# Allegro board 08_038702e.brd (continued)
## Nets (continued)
IO_L01_13_JX2_P: JX2.1(N1) U1.AA25(IO_L1P_T0_13)
IO_L01_33_JX1_N: JX1.37(N19) U1.F4(IO_L1N_T0_33)
IO_L01_33_JX1_P: JX1.35(N18) U1.G4(IO_L1P_T0_33)
IO_L01_34_JX4_N: JX4.21(N11) U1.H11(IO_L1N_T0_34)
IO_L01_34_JX4_P: JX4.19(N10) U1.J11(IO_L1P_T0_34)
IO_L01_35_RX_D0_N: U1.E12(IO_L1N_T0_AD0N_35) U17.K11(P1_D0/RX_D0_N)
IO_L01_35_RX_D0_P: U1.F12(IO_L1P_T0_AD0P_35) U17.J12(P1_D1/RX_D0_P)
IO_L02_12_JX3_N: JX3.27(N14) U1.AC11(IO_L2N_T0_12)
IO_L02_12_JX3_P: JX3.25(N13) U1.AB12(IO_L2P_T0_12)
IO_L02_13_JX2_N: JX2.4(N2) U1.AC26(IO_L2N_T0_13)
IO_L02_13_JX2_P: JX2.2(N1) U1.AB26(IO_L2P_T0_13)
IO_L02_33_JX1_N: JX1.43(N22) U1.D3(IO_L2N_T0_33)
IO_L02_33_JX1_P: JX1.41(N21) U1.D4(IO_L2P_T0_33)
IO_L02_34_JX4_N: JX4.22(N11) U1.G5(IO_L2N_T0_34)
IO_L02_34_JX4_P: JX4.20(N10) U1.G6(IO_L2P_T0_34)
IO_L02_35_RX_D1_N: U1.D10(IO_L2N_T0_AD8N_35) U17.K10(P1_D2/RX_D1_N)
IO_L02_35_RX_D1_P: U1.E10(IO_L2P_T0_AD8P_35) U17.J11(P1_D3/RX_D1_P)
IO_L03_12_JX3_N: JX3.28(N14) U1.AA10(IO_L3N_T0_DQS_12)
IO_L03_12_JX3_P: JX3.26(N13) U1.Y10(IO_L3P_T0_DQS_12)
IO_L03_13_JX2_N: JX2.7(N4) U1.AE26(IO_L3N_T0_DQS_13)
IO_L03_13_JX2_P: JX2.5(N3) U1.AE25(IO_L3P_T0_DQS_13)
IO_L03_33_JX1_N: JX1.44(N22) U1.F2(IO_L3N_T0_DQS_33)
IO_L03_33_JX1_P: JX1.42(N21) U1.G2(IO_L3P_T0_DQS_33)
IO_L03_34_JX4_N: JX4.27(N14) U1.G9(IO_L3N_T0_DQS_34)
IO_L03_34_JX4_P: JX4.25(N13) R53.1(N1) U1.H9(PUDC_B)
IO_L03_35_RX_D2_N: U1.F10(IO_L3N_T0_DQS_AD1N_35) U17.K9(P1_D4/RX_D2_N)
IO_L03_35_RX_D2_P: U1.G10(IO_L3P_T0_DQS_AD1P_35) U17.J10(P1_D5/RX_D2_P)
IO_L04_12_JX3_N: JX3.33(N17) U1.AB10(IO_L4N_T0_12)
IO_L04_12_JX3_P: JX3.31(N16) U1.AB11(IO_L4P_T0_12)
IO_L04_13_JX2_N: JX2.8(N4) U1.AD26(IO_L4N_T0_13)
IO_L04_13_JX2_P: JX2.6(N3) U1.AD25(IO_L4P_T0_13)
IO_L04_33_JX1_N: JX1.49(N25) U1.C1(IO_L4N_T0_33)
IO_L04_33_JX1_P: JX1.47(N24) U1.D1(IO_L4P_T0_33)
IO_L04_34_JX4_N: JX4.28(N14) U1.H6(IO_L4N_T0_34)
IO_L04_34_JX4_P: JX4.26(N13) U1.H7(IO_L4P_T0_34)
IO_L04_35_RX_D3_N: U1.D11(IO_L4N_T0_35) U17.K8(P1_D6/RX_D3_N)
IO_L04_35_RX_D3_P: U1.E11(IO_L4P_T0_35) U17.J9(P1_D7/RX_D3_P)
IO_L05_12_JX3_N: JX3.44(N22) U1.Y13(IO_L5N_T0_12)
IO_L05_12_JX3_P: JX3.42(N21) U1.W13(IO_L5P_T0_12)
IO_L05_33_JX1_N: JX1.56(N3) U1.E1(IO_L5N_T0_33)
IO_L05_33_JX1_P: JX1.54(N2) U1.E2(IO_L5P_T0_33)
IO_L05_34_JX4_N: JX4.33(N17) U1.J9(IO_L5N_T0_34)
IO_L05_34_JX4_P: JX4.31(N16) U1.J10(IO_L5P_T0_34)
IO_L05_35_RX_D4_N: U1.G11(IO_L5N_T0_AD9N_35) U17.K7(P1_D8/RX_D4_N)
IO_L05_35_RX_D4_P: U1.G12(IO_L5P_T0_AD9P_35) U17.J8(P1_D9/RX_D4_P)
IO_L06_12_JX3_N: JX3.66(N8) U1.AA12(IO_L6N_T0_VREF_12)
IO_L06_12_JX3_P: JX3.64(N7) U1.AA13(IO_L6P_T0_12)
IO_L06_13_JX2_N: JX2.20(N10) U1.AB24(IO_L6N_T0_VREF_13)
IO_L06_13_JX2_P: JX2.18(N9) U1.AA24(IO_L6P_T0_13)
IO_L06_33_JX1_N: JX1.63(N7) U1.E3(IO_L6N_T0_VREF_33)
IO_L06_33_JX1_P: JX1.61(N6) U1.F3(IO_L6P_T0_33)
IO_L06_34_JX4_N: JX4.34(N17) U1.H8(IO_L6N_T0_VREF_34)
IO_L06_34_JX4_P: JX4.32(N16) U1.J8(IO_L6P_T0_34)
IO_L06_35_RX_D5_N: U1.E13(IO_L6N_T0_VREF_35) U17.J7(P1_D10/RX_D5_N)
IO_L06_35_RX_D5_P: U1.F13(IO_L6P_T0_35) U17.H8(P1_D11/RX_D5_P)
IO_L07_12_JX3_N: JX3.75(N13) U1.AD10(IO_L7N_T1_12)
IO_L07_12_JX3_P: JX3.73(N12) U1.AE10(IO_L7P_T1_12)
IO_L07_13_JX2_N: JX2.25(N13) U1.AF22(IO_L7N_T1_13)
IO_L07_13_JX2_P: JX2.23(N12) U1.AE22(IO_L7P_T1_13)
IO_L07_33_JX1_N: JX1.64(N7) U1.H1(IO_L7N_T1_33)
IO_L07_33_JX1_P: JX1.62(N6) U1.J1(IO_L7P_T1_33)
IO_L07_34_JX4_N: JX4.37(N19) U1.E5(IO_L7N_T1_34)
IO_L07_34_JX4_P: JX4.35(N18) U1.F5(IO_L7P_T1_34)
IO_L07_35_RX_FRAME_N: U1.H12(IO_L7N_T1_AD2N_35) U17.G7(RX_FRAME_N)
IO_L07_35_RX_FRAME_P: U1.H13(IO_L7P_T1_AD2P_35) U17.G8(RX_FRAME_P)
IO_L08_12_JX3_N: JX3.76(N13) U1.AF12(IO_L8N_T1_12)
IO_L08_12_JX3_P: JX3.74(N12) U1.AE12(IO_L8P_T1_12)
IO_L08_13_JX2_N: JX2.26(N13) U1.AF23(IO_L8N_T1_13)
IO_L08_13_JX2_P: JX2.24(N12) U1.AE23(IO_L8P_T1_13)
IO_L08_33_JX1_N: JX1.69(N10) U1.H3(IO_L8N_T1_33)
IO_L08_33_JX1_P: JX1.67(N9) U1.H4(IO_L8P_T1_33)
IO_L08_34_JX4_N: JX4.38(N19) U1.D8(IO_L8N_T1_34)
IO_L08_34_JX4_P: JX4.36(N18) U1.D9(IO_L8P_T1_34)
IO_L08_35_FB_CLK_N: U1.J13(IO_L8N_T1_AD10N_35) U17.G10(FB_CLK_N)
IO_L08_35_FB_CLK_P: U1.K13(IO_L8P_T1_AD10P_35) U17.F10(FB_CLK_P)
IO_L09_12_JX3_N: JX3.81(N16) U1.AF10(IO_L9N_T1_DQS_12)
IO_L09_12_JX3_P: JX3.79(N15) U1.AE11(IO_L9P_T1_DQS_12)
IO_L09_13_JX2_N: JX2.31(N16) U1.AB22(IO_L9N_T1_DQS_13)
IO_L09_13_JX2_P: JX2.29(N15) U1.AB21(IO_L9P_T1_DQS_13)
IO_L09_33_JX1_N: JX1.70(N10) U1.K1(IO_L9N_T1_DQS_33)
IO_L09_33_JX1_P: JX1.68(N9) U1.K2(IO_L9P_T1_DQS_33)
IO_L09_34_JX4_N: JX4.43(N22) U1.E8(IO_L9N_T1_DQS_34)
IO_L09_34_JX4_P: JX4.41(N21) U1.F9(IO_L9P_T1_DQS_34)
IO_L09_35_TX_FRAME_N: U1.J15(IO_L9N_T1_DQS_AD3N_35) U17.H9(TX_FRAME_N)
IO_L09_35_TX_FRAME_P: U1.K15(IO_L9P_T1_DQS_AD3P_35) U17.G9(TX_FRAME_P)
IO_L10_12_JX3_N: JX3.82(N16) U1.AF13(IO_L10N_T1_12)
IO_L10_12_JX3_P: JX3.80(N15) U1.AE13(IO_L10P_T1_12)
IO_L10_13_JX2_N: JX2.32(N16) U1.AA23(IO_L10N_T1_13)
IO_L10_13_JX2_P: JX2.30(N15) U1.AA22(IO_L10P_T1_13)
IO_L10_33_JX1_N: JX1.75(N13) U1.G1(IO_L10N_T1_33)
IO_L10_33_JX1_P: JX1.73(N12) U1.H2(IO_L10P_T1_33)
IO_L10_34_JX4_N: JX4.44(N22) U1.D5(IO_L10N_T1_34)
IO_L10_34_JX4_P: JX4.42(N21) U1.E6(IO_L10P_T1_34)
IO_L10_35_EN_AGC: U1.G16(IO_L10P_T1_AD11P_35) U17.G5(EN_AGC)
IO_L10_35_SYNC_IN: R111.2(N2) U1.G15(IO_L10N_T1_AD11N_35) U17.H5(SYNC_IN)
IO_L11_35_ENABLE: U1.G14(IO_L11P_T1_SRCC_35) U17.G6(ENABLE)
IO_L11_35_TXNRX: U1.F14(IO_L11N_T1_SRCC_35) U17.H4(TXNRX)
IO_L11_SRCC_12_JX3_N: JX3.87(N19) U1.AD11(IO_L11N_T1_SRCC_12)
IO_L11_SRCC_12_JX3_P: JX3.85(N18) U1.AC12(IO_L11P_T1_SRCC_12)
IO_L11_SRCC_13_JX2_N: JX2.37(N19) U1.AD24(IO_L11N_T1_SRCC_13)
IO_L11_SRCC_13_JX2_P: JX2.35(N18) U1.AD23(IO_L11P_T1_SRCC_13)
IO_L11_SRCC_33_JX1_N: JX1.76(N13) U1.K3(IO_L11N_T1_SRCC_33)
IO_L11_SRCC_33_JX1_P: JX1.74(N12) U1.L3(IO_L11P_T1_SRCC_33)
IO_L11_SRCC_34_JX4_N: JX4.47(N24) U1.E7(IO_L11N_T1_SRCC_34)
IO_L11_SRCC_34_JX4_P: JX4.45(N23) U1.F8(IO_L11P_T1_SRCC_34)
IO_L12_MRCC_12_JX3_N: JX3.88(N19) U1.AD13(IO_L12N_T1_MRCC_12)
IO_L12_MRCC_12_JX3_P: JX3.86(N18) U1.AC13(IO_L12P_T1_MRCC_12)
IO_L12_MRCC_13_JX2_N: JX2.38(N19) U1.AC24(IO_L12N_T1_MRCC_13)
IO_L12_MRCC_13_JX2_P: JX2.36(N18) U1.AC23(IO_L12P_T1_MRCC_13)
IO_L12_MRCC_33_JX1_N: JX1.83(N17) U1.J3(IO_L12N_T1_MRCC_33)
IO_L12_MRCC_33_JX1_P: JX1.81(N16) U1.J4(IO_L12P_T1_MRCC_33)
IO_L12_MRCC_34_JX4_N: JX4.48(N24) U1.F7(IO_L12N_T1_MRCC_34)
IO_L12_MRCC_34_JX4_P: JX4.46(N23) U1.G7(IO_L12P_T1_MRCC_34)
IO_L12_MRCC_35_DATA_CLK_N: U1.H14(IO_L12N_T1_MRCC_35) U17.H11(DATA_CLK_N)
IO_L12_MRCC_35_DATA_CLK_P: U1.J14(IO_L12P_T1_MRCC_35) U17.G11(DATA_CLK_P)
IO_L13_35_TX_D0_N: U1.D14(IO_L13N_T2_MRCC_35) U17.E12(P0_D0/TX_D0_N)
IO_L13_35_TX_D0_P: U1.D15(IO_L13P_T2_MRCC_35) U17.D11(P0_D1/TX_D0_P)
IO_L13_MRCC_12_JX3_N: JX3.93(N22) U1.AD14(IO_L13N_T2_MRCC_12)
IO_L13_MRCC_12_JX3_P: JX3.91(N21) U1.AC14(IO_L13P_T2_MRCC_12)
IO_L13_MRCC_13_JX2_N: JX2.43(N22) U1.AD21(IO_L13N_T2_MRCC_13)
IO_L13_MRCC_13_JX2_P: JX2.41(N21) U1.AD20(IO_L13P_T2_MRCC_13)
IO_L13_MRCC_33_JX1_N: JX1.84(N17) U1.M5(IO_L13N_T2_MRCC_33)
IO_L13_MRCC_33_JX1_P: JX1.82(N16) U1.M6(IO_L13P_T2_MRCC_33)
IO_L13_MRCC_34_JX4_N: JX4.53(N2) U1.C7(IO_L13N_T2_MRCC_34)
IO_L13_MRCC_34_JX4_P: JX4.51(N1) U1.C8(IO_L13P_T2_MRCC_34)
IO_L14_35_TX_D1_N: U1.E15(IO_L14N_T2_AD4N_SRCC_35) U17.E11(P0_D2/TX_D1_N)
IO_L14_35_TX_D1_P: U1.F15(IO_L14P_T2_AD4P_SRCC_35) U17.D10(P0_D3/TX_D1_P)
IO_L14_SRCC_12_JX3_N: JX3.94(N22) U1.AB14(IO_L14N_T2_SRCC_12)
IO_L14_SRCC_12_JX3_P: JX3.92(N21) U1.AB15(IO_L14P_T2_SRCC_12)
IO_L14_SRCC_13_JX2_N: JX2.44(N22) U1.AC22(IO_L14N_T2_SRCC_13)
IO_L14_SRCC_13_JX2_P: JX2.42(N21) U1.AC21(IO_L14P_T2_SRCC_13)
IO_L14_SRCC_33_JX1_N: JX1.50(N25) U1.L4(IO_L14N_T2_SRCC_33)
IO_L14_SRCC_33_JX1_P: JX1.48(N24) U1.L5(IO_L14P_T2_SRCC_33)
IO_L14_SRCC_34_JX4_N: JX4.54(N2) U1.C6(IO_L14N_T2_SRCC_34)
IO_L14_SRCC_34_JX4_P: JX4.52(N1) U1.D6(IO_L14P_T2_SRCC_34)
IO_L15_12_JX3_N: JX3.99(N25) U1.AD15(IO_L15N_T2_DQS_12)
IO_L15_12_JX3_P: JX3.97(N24) U1.AD16(IO_L15P_T2_DQS_12)
IO_L15_13_JX2_N: JX2.49(N25) U1.AF20(IO_L15N_T2_DQS_13)
IO_L15_13_JX2_P: JX2.47(N24) U1.AF19(IO_L15P_T2_DQS_13)
IO_L15_33_JX1_N: JX1.55(N3) U1.N2(IO_L15N_T2_DQS_33)
IO_L15_33_JX1_P: JX1.53(N2) U1.N3(IO_L15P_T2_DQS_33)
IO_L15_34_JX4_N: JX4.59(N5) U1.B9(IO_L15N_T2_DQS_34)
IO_L15_34_JX4_P: JX4.57(N4) U1.C9(IO_L15P_T2_DQS_34)
IO_L15_35_TX_D2_N: U1.C16(IO_L15N_T2_DQS_AD12N_35) U17.E10(P0_D4/TX_D2_N)
IO_L15_35_TX_D2_P: U1.C17(IO_L15P_T2_DQS_AD12P_35) U17.D9(P0_D5/TX_D2_P)
IO_L16_12_JX3_N: JX3.100(N25) U1.AF14(IO_L16N_T2_12)
IO_L16_12_JX3_P: JX3.98(N24) U1.AF15(IO_L16P_T2_12)
IO_L16_13_JX2_N: JX2.50(N25) U1.AE21(IO_L16N_T2_13)
IO_L16_13_JX2_P: JX2.48(N24) U1.AE20(IO_L16P_T2_13)
IO_L16_33_JX1_N: JX1.13(N7) U1.L2(IO_L16N_T2_33)
IO_L16_33_JX1_P: JX1.11(N6) U1.M2(IO_L16P_T2_33)
IO_L16_34_JX4_N: JX4.60(N5) U1.A10(IO_L16N_T2_34)
IO_L16_34_JX4_P: JX4.58(N4) U1.B10(IO_L16P_T2_34)
IO_L16_35_TX_D3_N: U1.D16(IO_L16N_T2_35) U17.E9(P0_D6/TX_D3_N)
IO_L16_35_TX_D3_P: U1.E16(IO_L16P_T2_35) U17.D8(P0_D7/TX_D3_P)
IO_L17_12_JX2_N: JX2.84(N17) U1.AE15(IO_L17N_T2_12)
IO_L17_12_JX2_P: JX2.82(N16) U1.AE16(IO_L17P_T2_12)
IO_L17_13_JX2_N: JX2.55(N3) U1.AD19(IO_L17N_T2_13)
IO_L17_13_JX2_P: JX2.53(N2) U1.AD18(IO_L17P_T2_13)
IO_L17_33_JX1_N: JX1.14(N7) U1.M4(IO_L17N_T2_33)
IO_L17_33_JX1_P: JX1.12(N6) U1.N4(IO_L17P_T2_33)
IO_L17_34_JX4_N: JX4.69(N10) U1.A8(IO_L17N_T2_34)
IO_L17_34_JX4_P: JX4.67(N9) U1.A9(IO_L17P_T2_34)
IO_L17_35_TX_D4_N: U1.B15(IO_L17N_T2_AD5N_35) U17.E8(P0_D8/TX_D4_N)
IO_L17_35_TX_D4_P: U1.B16(IO_L17P_T2_AD5P_35) U17.D7(P0_D9/TX_D4_P)
IO_L18_12_JX2_N: JX2.83(N17) U1.AF17(IO_L18N_T2_12)
IO_L18_12_JX2_P: JX2.81(N16) U1.AE17(IO_L18P_T2_12)
IO_L18_13_JX2_N: JX2.56(N3) U1.AF18(IO_L18N_T2_13)
IO_L18_13_JX2_P: JX2.54(N2) U1.AE18(IO_L18P_T2_13)
IO_L18_33_JX1_N: JX1.19(N10) U1.M1(IO_L18N_T2_33)
IO_L18_33_JX1_P: JX1.17(N9) U1.N1(IO_L18P_T2_33)
IO_L18_34_JX4_N: JX4.70(N10) U1.A7(IO_L18N_T2_34)
IO_L18_34_JX4_P: JX4.68(N9) U1.B7(IO_L18P_T2_34)
IO_L18_35_TX_D5_N: U1.A17(IO_L18N_T2_AD13N_35) U17.F8(P0_D10/TX_D5_N)
IO_L18_35_TX_D5_P: U1.B17(IO_L18P_T2_AD13P_35) U17.E7(P0_D11/TX_D5_P)
IO_L19_12_JX2_N: JX2.90(N20) U1.AA17(IO_L19N_T3_VREF_12)
IO_L19_12_JX2_P: JX2.88(N19) U1.Y17(IO_L19P_T3_12)
IO_L19_13_JX2_N: JX2.63(N7) U1.Y20(IO_L19N_T3_VREF_13)
IO_L19_13_JX2_P: JX2.61(N6) U1.W20(IO_L19P_T3_13)
IO_L19_33_JX1_N: JX1.20(N10) U1.L7(IO_L19N_T3_VREF_33)
IO_L19_33_JX1_P: JX1.18(N9) U1.M7(IO_L19P_T3_33)
IO_L19_34_JX4_N: JX4.75(N13) U1.C3(IO_L19N_T3_VREF_34)
IO_L19_34_JX4_P: JX4.73(N12) U1.C4(IO_L19P_T3_34)
IO_L19_35_CTRL_OUT0: U1.D13(IO_L19P_T3_35) U17.D4(CTRL_OUT0)
IO_L19_35_CTRL_OUT1: U1.C13(IO_L19N_T3_VREF_35) U17.E4(CTRL_OUT1)
IO_L20_12_JX2_N: JX2.89(N20) U1.AB16(IO_L20N_T3_12)
IO_L20_12_JX2_P: JX2.87(N19) U1.AB17(IO_L20P_T3_12)
IO_L20_13_JX2_N: JX2.64(N7) U1.AB20(IO_L20N_T3_13)
IO_L20_13_JX2_P: JX2.62(N6) U1.AA20(IO_L20P_T3_13)
IO_L20_33_JX1_N: JX1.25(N13) U1.J5(IO_L20N_T3_33)
IO_L20_33_JX1_P: JX1.23(N12) U1.K5(IO_L20P_T3_33)
IO_L20_34_JX4_N: JX4.76(N13) U1.B4(IO_L20N_T3_34)
IO_L20_34_JX4_P: JX4.74(N12) U1.B5(IO_L20P_T3_34)
IO_L20_35_CTRL_OUT2: U1.C14(IO_L20P_T3_AD6P_35) U17.E5(CTRL_OUT2)
IO_L20_35_CTRL_OUT3: U1.B14(IO_L20N_T3_AD6N_35) U17.E6(CTRL_OUT3)
IO_L21_12_JX2_N: JX2.95(N23) U1.AC16(IO_L21N_T3_DQS_12)
IO_L21_12_JX2_P: JX2.93(N22) U1.AC17(IO_L21P_T3_DQS_12)
IO_L21_13_JX2_N: JX2.69(N10) U1.AC19(IO_L21N_T3_DQS_13)
IO_L21_13_JX2_P: JX2.67(N9) U1.AC18(IO_L21P_T3_DQS_13)
IO_L21_33_JX1_N: JX1.26(N13) U1.L8(IO_L21N_T3_DQS_33)
IO_L21_33_JX1_P: JX1.24(N12) U1.M8(IO_L21P_T3_DQS_33)
IO_L21_34_JX4_N: JX4.79(N15) U1.A5(IO_L21N_T3_DQS_34)
IO_L21_34_JX4_P: JX4.77(N14) U1.B6(IO_L21P_T3_DQS_34)
IO_L21_35_CTRL_OUT4: U1.A15(IO_L21P_T3_DQS_AD14P_35) U17.F6(CTRL_OUT4)
IO_L21_35_CTRL_OUT5: U1.A14(IO_L21N_T3_DQS_AD14N_35) U17.F5(CTRL_OUT5)
IO_L22_12_JX2_N: JX2.96(N23) U1.AA14(IO_L22N_T3_12)
IO_L22_12_JX2_P: JX2.94(N22) U1.AA15(IO_L22P_T3_12)
IO_L22_13_JX2_N: JX2.70(N10) U1.AB19(IO_L22N_T3_13)
IO_L22_13_JX2_P: JX2.68(N9) U1.AA19(IO_L22P_T3_13)
IO_L22_33_JX1_N: JX1.31(N16) U1.J6(IO_L22N_T3_33)
IO_L22_33_JX1_P: JX1.29(N15) U1.K6(IO_L22P_T3_33)
IO_L22_34_JX4_N: JX4.80(N15) U1.A3(IO_L22N_T3_34)
IO_L22_34_JX4_P: JX4.78(N14) U1.A4(IO_L22P_T3_34)
IO_L22_35_CTRL_OUT6: U1.C12(IO_L22P_T3_AD7P_35) U17.F4(CTRL_OUT6)
IO_L22_35_CTRL_OUT7: U1.B12(IO_L22N_T3_AD7N_35) U17.G4(CTRL_OUT7)
IO_L23_12_JX2_N: JX2.99(N25) U1.Y15(IO_L23N_T3_12)
IO_L23_12_JX2_P: JX2.97(N24) U1.Y16(IO_L23P_T3_12)
IO_L23_13_JX2_N: JX2.75(N13) U1.W19(IO_L23N_T3_13)
IO_L23_13_JX2_P: JX2.73(N12) U1.W18(IO_L23P_T3_13)
IO_L23_33_JX1_N: JX1.32(N16) U1.N6(IO_L23N_T3_33)
IO_L23_33_JX1_P: JX1.30(N15) U1.N7(IO_L23P_T3_33)
IO_L23_34_CTRL_IN0: U1.C2(IO_L23P_T3_34) U22.13(B0)
IO_L23_34_CTRL_IN1: U1.B1(IO_L23N_T3_34) U22.12(B1)
IO_L23_35_SPI_CLK: U1.B11(IO_L23N_T3_35) U17.J5(SPI_CLK)
IO_L23_35_SPI_ENB: U1.C11(IO_L23P_T3_35) U17.K6(SPI_ENB)
IO_L24_12_JX4_N: JX4.15(N8) U1.W15(IO_L24N_T3_12)
IO_L24_12_JX4_P: JX4.13(N7) U1.W16(IO_L24P_T3_12)
IO_L24_13_JX2_N: JX2.76(N13) U1.AA18(IO_L24N_T3_13)
IO_L24_13_JX2_P: JX2.74(N12) U1.Y18(IO_L24P_T3_13)
IO_L24_33_JX1_N: JX1.38(N19) U1.K7(IO_L24N_T3_33)
IO_L24_33_JX1_P: JX1.36(N18) U1.K8(IO_L24P_T3_33)
IO_L24_34_CTRL_IN2: U1.B2(IO_L24P_T3_34) U22.11(B2)
IO_L24_34_CTRL_IN3: U1.A2(IO_L24N_T3_34) U22.10(B3)
IO_L24_35_SPI_DI: U1.A13(IO_L24P_T3_AD15P_35) U17.J4(SPI_DI)
IO_L24_35_SPI_DO: U1.A12(IO_L24N_T3_AD15N_35) U17.L6(SPI_DO)
J3-9: J3.9(N9) R36.2(N2) U5.7(S2B)
JTAG_TCK: JX1.1(N1) U1.W12(TCK_0)
JTAG_TDI: JX1.4(N2) U1.V11(TDI_0)
JTAG_TDO: JX1.3(N2) U1.W10(TDO_0)
JTAG_TMS: JX1.2(N1) U1.W11(TMS_0)
JX3_SD1_CDN: JX3.41(N21) U5.9(S2A)
JX_MGTAVCC: JX3.5(N3) JX3.7(N4) JX3.9(N5) JX3.11(N6) Q8.1(D1) Q8.2(D2) Q8.5(D3) Q8.6(D4) U7.3(VX3)
JX_MGTAVTT: JX3.30(N15) JX3.32(N16) Q7.1(D1) Q7.2(D2) Q7.5(D3) Q7.6(D4) U7.4(VX4)
JX_VCCO_12: JX1.78(N14) JX1.79(N15) JX1.80(N15) Q11.1(D1) Q11.2(D2) Q11.5(D3) Q11.6(D4) Q11.PAD1(D5) R70.1(N1)
JX_VCCO_12_SEQ: R69.1(N1) R70.2(N2) U7.7(VP2)
JX_VCCO_13: JX2.98(N24) JX3.45(N23) JX3.46(N23) Q9.1(D1) Q9.2(D2) Q9.5(D3) Q9.6(D4) Q9.PAD1(D5) R72.1(N1)
JX_VCCO_13_SEQ: R71.1(N1) R72.2(N2) U7.8(VP3)
JX_VCCO_33_34: JX2.78(N14) JX2.79(N15) JX2.80(N15) Q10.1(D1) Q10.2(D2) Q10.5(D3) Q10.6(D4) R73.1(N1)
JX_VCCO_33_34_SEQ: R73.2(N2) R74.1(N1) U7.9(VP4)
JX_VIN: D1.1(N1) JX1.57(N4) JX1.58(N4) JX1.59(N5) JX1.60(N5) JX2.12(N6) JX2.57(N4) JX2.58(N4) JX2.59(N5) JX2.60(N5) Q13.1(D1) Q13.2(D2) Q13.5(D3) Q13.6(D4) Q13.PAD1(D5)
MGTAVCC: C64.1(N1) C220.1(N1) C222.1(N1) C227.1(N1) C229.1(N1) C231.1(N1) C233.1(N1) C235.1(N1) C237.1(N1) C239.1(N1) Q8.4(S) U1.AA4(MGTAVCC1) U1.AA8(MGTAVCC2) U1.AB6(MGTAVCC3) U1.AC8(MGTAVCC4) U1.AD6(MGTAVCC5) U1.AE8(MGTAVCC6) U1.R4(MGTAVCC7) U1.T6(MGTAVCC8) U1.U4(MGTAVCC9) U1.Y6(MGTAVCC10)
MGTAVCC_EN: Q8.3(G) U7.25(PDO6)
MGTAVTT: C221.1(N1) C223.1(N1) C228.1(N1) C230.1(N1) C232.1(N1) C234.1(N1) C236.1(N1) C238.1(N1) C240.1(N1) C241.1(N1) Q7.4(S) R10.1(N1) U1.AB2(MGTAVTT1) U1.AB7(MGTAVTTRCAL_112) U1.AC4(MGTAVTT2) U1.AD2(MGTAVTT3) U1.AE4(MGTAVTT4) U1.AF2(MGTAVTT5) U1.AF6(MGTAVTT6) U1.T2(MGTAVTT7) U1.V2(MGTAVTT8) U1.W4(MGTAVTT9) U1.Y2(MGTAVTT10)
MGTAVTT_EN: Q7.3(G) U7.26(PDO5)
MGTREFCLK0_112_JX1_N: C45.1(N1) JX1.89(N20)
MGTREFCLK0_112_JX1_P: C47.1(N1) JX1.87(N19)
MGTREFCLK1_112_JX3_N: C48.1(N1) JX3.4(N2)
MGTREFCLK1_112_JX3_P: C46.1(N1) JX3.2(N1)
MGTXRX0_112_JX1_N: JX1.90(N20) U1.AB3(MGTXRXN0_112)
MGTXRX0_112_JX1_P: JX1.88(N19) U1.AB4(MGTXRXP0_112)
MGTXRX1_112_JX1_N: JX1.93(N22) U1.Y3(MGTXRXN1_112)
MGTXRX1_112_JX1_P: JX1.91(N21) U1.Y4(MGTXRXP1_112)
MGTXRX2_112_JX1_N: JX1.94(N22) U1.V3(MGTXRXN2_112)
MGTXRX2_112_JX1_P: JX1.92(N21) U1.V4(MGTXRXP2_112)
MGTXRX3_112_JX1_N: JX1.99(N25) U1.T3(MGTXRXN3_112)
MGTXRX3_112_JX1_P: JX1.97(N24) U1.T4(MGTXRXP3_112)
MGTXTX0_112_JX3_N: JX3.10(N5) U1.AA1(MGTXTXN0_112)
MGTXTX0_112_JX3_P: JX3.8(N4) U1.AA2(MGTXTXP0_112)
MGTXTX1_112_JX3_N: JX3.15(N8) U1.W1(MGTXTXN1_112)
MGTXTX1_112_JX3_P: JX3.13(N7) U1.W2(MGTXTXP1_112)
MGTXTX2_112_JX3_N: JX3.16(N8) U1.U1(MGTXTXN2_112)
MGTXTX2_112_JX3_P: JX3.14(N7) U1.U2(MGTXTXP2_112)
MGTXTX3_112_JX3_N: JX3.21(N11) U1.R1(MGTXTXN3_112)
MGTXTX3_112_JX3_P: JX3.19(N10) U1.R2(MGTXTXP3_112)
PG_1P8V: JX2.10(N5) R81.1(N1) U4.1(PG3) U19.4(EN) U20.4(EN)
PG_MODULE: JX2.11(N6) Q14.1(G) R43.2(N2) U7.21(PDO10)
PHY1_1V8: C74.1(N1) C78.1(N1) C206.1(N1) C212.1(N1) E14.2(N2) R11.1(N1) U10.10(VDDO_SEL) U10.11(VDDO_1) U10.49(VDDO_2) U10.52(VDDO_3)
PHY1_AVDD_1V8: C201.1(N1) C203.1(N1) C210.1(N1) C211.1(N1) C218.1(N1) C219.1(N1) U10.3(AVDD18_1) U10.19(AVDD18_2) U10.26(AVDD18_3) U10.35(AVDDC18) U10.38(AVDD18_4) U10.39(AVDD18_OUT) U24.5(VIN7)
PHY1_AVDD_3V3: C49.1(N1) C208.1(N1) C214.1(N1) C217.1(N1) E15.2(N2) U10.20(AVDD33_1) U10.25(AVDD33_2)
PHY1_DVDD_1V0: C58.1(N1) C63.1(N1) C73.1(N1) C75.1(N1) U10.6(DVDD_1) U10.40(DVDD_OUT) U10.42(DVDD_2)
PHY1_LED_0: Q2.1(G) R14.1(N1) U10.14(LED(0))
PHY1_LED_1: Q1.1(G) R13.1(N1) U10.13(LED(1))
PHY1_VDD_3V3: C50.1(N1) C224.1(N1) C225.1(N1) C226.1(N1) E16.2(N2) R15.1(N1) R16.1(N1) U10.36(REG_IN)
PS-SRST#: Q5.2(S) R7.2(N2) R19.1(N1) U1.A22(PS_SRST_B_501)
PS_1.35V_EN: U4.7(EN2) U7.22(PDO9)
PS_MIO00_500_JX4: JX4.97(N24) U1.E26(PS_MIO0_500)
PS_MIO01_500_QSPI0_SS_B: R28.2(N2) U1.D26(PS_MIO1_500) U13.C2(S#)
PS_MIO02_500_QSPI0_IO0: R120.1(N1) U1.E25(PS_MIO2_500) U13.D3(DQ0)
PS_MIO03_500_QSPI0_IO1: R119.1(N1) U1.D25(PS_MIO3_500) U13.D2(DQ1)
PS_MIO04_500_QSPI0_IO2: R121.1(N1) U1.F24(PS_MIO4_500) U13.C4(W#/VPP/DQ2)
PS_MIO05_500_QSPI0_IO3: R122.1(N1) U1.C26(PS_MIO5_500) U13.D4(HOLD#/DQ3)
PS_MIO06_500_QSPI0_SCLK: R116.1(N1) U1.F23(PS_MIO6_500) U13.B2(C)
PS_MIO07_500_USB_RESET_B: R31.2(N2) U1.E23(PS_MIO7_500) U15.27(RESETB)
PS_MIO08_500_ETH0_RESETN: R32.2(N2) U1.A24(PS_MIO8_500) U10.16(RESETN)
PS_MIO09_500_USB_CLK_PD: R27.1(N1) U1.D24(PS_MIO9_500) Y3.1(STANDBY)
PS_MIO10_500_JX4: JX4.87(N19) U1.A25(PS_MIO10_500)
PS_MIO11_500_JX4: JX4.88(N19) U1.B26(PS_MIO11_500)
PS_MIO12_500_JX4: JX4.86(N18) R60.2(N2)
PS_MIO13_500_JX4: JX4.91(N21) U1.B25(PS_MIO13_500)
PS_MIO14_500_JX4: JX4.93(N22) U1.D23(PS_MIO14_500)
PS_MIO15_500_JX4: JX4.85(N18) U1.C24(PS_MIO15_500)
PS_MIO16_501_ETH0_TX_CLK: U1.G21(PS_MIO16_501) U10.53(TX_CLK)
PS_MIO17_501_ETH0_TX_D0: U1.G17(PS_MIO17_501) U10.50(TXD(0))
PS_MIO18_501_ETH0_TX_D1: U1.G20(PS_MIO18_501) U10.51(TXD(1))
PS_MIO19_501_ETH0_TX_D2: U1.G19(PS_MIO19_501) U10.54(TXD(2))
PS_MIO20_501_ETH0_TX_D3: U1.H19(PS_MIO20_501) U10.55(TXD(3))
PS_MIO21_501_ETH0_TX_CTL: U1.F22(PS_MIO21_501) U10.56(TX_CTRL)
PS_MIO22_501_ETH0_RX_CLK: U1.G22(PS_MIO22_501) U10.46(RX_CLK)
PS_MIO23_501_ETH0_RX_D0: U1.F20(PS_MIO23_501) U10.44(RXD(0))
PS_MIO24_501_ETH0_RX_D1: U1.J19(PS_MIO24_501) U10.45(RXD(1))
PS_MIO25_501_ETH0_RX_D2: U1.F19(PS_MIO25_501) U10.47(RXD(2))
PS_MIO26_501_ETH0_RX_D3: U1.H17(PS_MIO26_501) U10.48(RXD(3))
PS_MIO27_501_ETH0_RX_CTL: U1.F18(PS_MIO27_501) U10.43(RX_CTRL)
PS_MIO28_501_USB0_D4: U1.J18(PS_MIO28_501) U15.7(DATA4)
PS_MIO29_501_USB0_DIR: U1.E20(PS_MIO29_501) U15.31(DIR)
PS_MIO30_501_USB0_STP: U1.K19(PS_MIO30_501) U15.29(STP)
PS_MIO31_501_USB0_NXT: U1.E21(PS_MIO31_501) U15.2(NXT)
PS_MIO32_501_USB0_D0: U1.K17(PS_MIO32_501) U15.3(DATA0)
PS_MIO33_501_USB0_D1: U1.E22(PS_MIO33_501) U15.4(DATA1)
PS_MIO34_501_USB0_D2: U1.J16(PS_MIO34_501) U15.5(DATA2)
PS_MIO35_501_USB0_D3: U1.D19(PS_MIO35_501) U15.6(DATA3)
PS_MIO36_501_USB0_CLK: U1.K16(PS_MIO36_501) U15.1(CLKOUT)
PS_MIO37_501_USB0_D5: U1.D20(PS_MIO37_501) U15.9(DATA5)
PS_MIO38_501_USB0_D6: U1.D21(PS_MIO38_501) U15.10(DATA6)
PS_MIO39_501_USB0_D7: U1.C21(PS_MIO39_501) U15.13(DATA7)
PS_MIO40_501_SD0_CLK: U1.C22(PS_MIO40_501) U11.9(CLKA)
PS_MIO41_501_SD0_CMD: U1.C19(PS_MIO41_501) U11.4(CMDA)
PS_MIO42_501_SD0_DATA0: U1.F17(PS_MIO42_501) U11.6(DAT0A)
PS_MIO43_501_SD0_DATA1: U1.D18(PS_MIO43_501) U11.7(DAT1A)
PS_MIO44_501_SD0_DATA2: U1.E18(PS_MIO44_501) U11.1(DAT2A)
PS_MIO45_501_SD0_DATA3: U1.C18(PS_MIO45_501) U11.3(DAT3A)
PS_MIO46_501_JX4: JX4.92(N21) R37.2(N2) U1.E17(PS_MIO46_501)
PS_MIO47_501_JX4: JX4.94(N22) R26.1(N1) U1.B19(PS_MIO47_501)
PS_MIO48_501_JX4: JX4.99(N25) U1.B21(PS_MIO48_501)
PS_MIO49_501_JX4: JX4.98(N24) U1.A18(PS_MIO49_501)
PS_MIO50_501_SD0_CD: U1.B22(PS_MIO50_501) U5.8(D2)
PS_MIO51_501_JX4: JX4.100(N25) U1.B20(PS_MIO51_501)
PS_MIO52_501_ETH0_MDC: U1.A20(PS_MIO52_501) U10.7(MDC)
PS_MIO53_501_ETH0_MDIO: R11.2(N2) U1.A19(PS_MIO53_501) U10.8(MDIO)
PWR_ENABLE: JX1.5(N3) R56.2(N2) U4.12(EN1) U18.20(EN)
PWR_GD: R306.1(N1) U7.37(AUX2) U9.7(PG) U19.5(PG) U20.5(PG)
PWR_GD_1.35V: R3.2(N2) R29.2(N2) SW1.1A(N1) SW1.1B(N2) U1.C23(PS_POR_B_500) U4.2(PG2) U4.6(PG1) U18.21(PGOOD)
REF_IN_OUT: C202.1(N1) U7.13(REFIN) U7.14(REFOUT)
RX1A_N: C8.2(N2) U17.M2(RX1A_N)
RX1A_P: C9.2(N2) U17.M1(RX1A_P)
RX1B_N: C51.2(N2) U17.J1(RX1B_N)
RX1B_P: C52.2(N2) U17.H1(RX1B_P)
RX2A_N: C10.2(N2) U17.A1(RX2A_N)
RX2A_P: C11.2(N2) U17.A2(RX2A_P)
RX2B_N: C53.2(N2) U17.F1(RX2B_N)
RX2B_P: C56.2(N2) U17.E1(RX2B_P)
S_IN_N: JP2.3(B) U10.2(S_INN)
S_IN_P: JP1.3(B) U10.1(S_INP)
S_OUT_N: JP4.3(B) U10.5(S_OUTN)
S_OUT_P: JP3.3(B) U10.4(S_OUTP)
SCL: JX2.17(N9) R58.2(N2) U1.AF24(IO_L5P_T0_13) U21.2(SCLA)
SCL_ADM1166: P1.A4(N4A) P1.B4(N4B) R51.2(N2) U7.35(SCL) U21.7(SCLB) U24.15(SCL)
SD_SEL: S1.2(C) U5.5(IN2) U11.24(SEL)
SDA: JX2.19(N10) R57.2(N2) U1.AF25(IO_L5N_T0_13) U21.3(SDAA)
SDA_ADM1166: P1.A3(N3A) P1.B3(N3B) R52.2(N2) U7.36(SDA) U21.6(SDAB) U24.14(SDA)
SDIO_CLKB0: J3.5(N5) U11.19(CLKB0)
SDIO_CLKB1: JX3.43(N22) U11.13(CLKB1)
SDIO_CMDB0: J3.3(N3) R109.2(N2) U11.20(CMDB0)
SDIO_CMDB1: JX3.34(N17) R4.2(N2) U11.12(CMDB1)
SDIO_DAT0B0: J3.7(N7) U11.18(DAT0B0)
SDIO_DAT0B1: JX3.37(N19) U11.14(DAT0B1)
SDIO_DAT1B0: J3.8(N8) U11.16(DAT1B0)
SDIO_DAT1B1: JX3.36(N18) U11.15(DAT1B1)
SDIO_DAT2B0: J3.1(N1) U11.23(DAT2B0)
SDIO_DAT2B1: JX3.39(N20) U11.8(DAT2B1)
SDIO_DAT3B0: J3.2(N2) U11.22(DAT3B0)
SDIO_DAT3B1: JX3.38(N19) U11.10(DAT3B1)
SW1: L5.1(N1) U4.15(SW1)
SW2: L6.1(N1) U4.4(SW2)
SW3: L7.1(N1) U4.20(SW3)
TX1A_N: C25.1(N1) L8.2(N2) U17.M8(TX1A_N)
TX1A_P: C26.1(N1) L9.2(N2) U17.M7(TX1A_P)
TX1B_N: C29.1(N1) L1.2(N2) U17.M10(TX1B_N)
TX1B_P: C30.1(N1) L2.2(N2) U17.M9(TX1B_P)
TX2A_N: C32.1(N1) L10.2(N2) U17.A7(TX2A_N)
TX2A_P: C33.1(N1) L11.2(N2) U17.A8(TX2A_P)
TX2B_N: C34.1(N1) L3.2(N2) U17.A9(TX2B_N)
TX2B_P: C35.1(N1) L4.2(N2) U17.A10(TX2B_P)
TX_MON1: C6.2(N2) U17.M5(TX_MON1)
TX_MON2: C7.2(N2) U17.A5(TX_MON2)
TX_VCO_1P1V_SUPPLY: C104.2(N2) R123.1(N1) U17.A11(VDDA1P1_TX_VCO) U17.B11(TX_VCO_LDO_OUT)
UNNAMED_2_CAP_I87_N1: C242.1(N1) U10.41(REGCAP2)
UNNAMED_2_CAP_I87_N2: C242.2(N2) U10.37(REGCAP1)
UNNAMED_2_CAP_I88_N1: C60.1(N1) U10.34(XTAL_IN) Y2.3(N2)
UNNAMED_2_CAP_I90_N1: C59.1(N1) U10.33(XTAL_OUT) Y2.1(N1)
UNNAMED_2_DIO6PV8_I47_REF1: R178.2(N2) U16.2(REF1)
UNNAMED_2_IC88E151X_I86_CONFIG: R12.2(N2) U10.15(CONFIG)
UNNAMED_2_IC88E151X_I86_RSET: R50.1(N1) U10.30(RSET)
UNNAMED_2_ICUSB3320C_I42_RBIAS: R176.1(N1) U15.24(RBIAS)
UNNAMED_2_ICUSB3320C_I42_REFCLK: R175.1(N1) U15.26(REFCLK)
UNNAMED_2_ICXC7Z035_I20_PSMIOVR: R191.1(N1) R194.2(N2) U1.H18(PS_MIO_VREF_501)
UNNAMED_2_RES_I50_N2: R175.2(N2) Y3.3(OUTPUT)
UNNAMED_2_RES_I105_N1: Q4.3(D) R18.1(N1)
UNNAMED_2_RES_I108_N2: Q2.3(D) Q4.1(G) R16.2(N2)
UNNAMED_2_RES_I112_N1: Q3.3(D) R17.1(N1)
UNNAMED_2_RES_I114_N2: Q1.3(D) Q3.1(G) R15.2(N2)
UNNAMED_3_ADM1166_I104_A0: R30.2(N2) R38.1(N1) U7.33(A0)
UNNAMED_3_ADM1166_I104_A1: R39.2(N2) R40.1(N1) U7.34(A1)
UNNAMED_3_ADM1166_I104_DAC1: R41.1(N1) U7.15(DAC1)
UNNAMED_3_ADM1166_I104_DAC2: R42.1(N1) U7.16(DAC2)
UNNAMED_3_ADM1166_I104_DAC3: R44.1(N1) U7.17(DAC3)
UNNAMED_3_ADM1166_I104_DAC4: R45.1(N1) U7.18(DAC4)
UNNAMED_3_ADM1166_I104_VCCP: C204.1(N1) U7.32(VCCP)
UNNAMED_3_ICN25Q256AV2_I216_RES: R19.2(N2) U13.A4(RESET/NC)
UNNAMED_3_ICXC7Z035_I94_PSCLK50: R114.2(N2) U1.B24(PS_CLK_500)
UNNAMED_3_ICXC7Z035_I94_PSMIO12: R60.1(N1) U1.A23(PS_MIO12_500)
UNNAMED_3_RES_I9_N1: R114.1(N1) Y1.3(OUTPUT)
UNNAMED_3_RES_I30_N2: R121.2(N2) S3.2(C)
UNNAMED_3_RES_I33_N2: R122.2(N2) S4.2(C)
UNNAMED_3_RES_I237_N2: R76.2(N2) R77.1(N1) Y1.1(STANDBY)
UNNAMED_4_CN100PODDEVEN_I16_N4: JP3.2(COM) JX3.58(N4)
UNNAMED_4_CN100PODDEVEN_I16_N5: JP4.2(COM) JX3.60(N5)
UNNAMED_4_CN100PODDEVEN_I17_N4: JP1.2(COM) JX3.57(N4)
UNNAMED_4_CN100PODDEVEN_I17_N5: JP2.2(COM) JX3.59(N5)
UNNAMED_5_ICMT41K256M16_I195_ZQ: R165.1(N1) U2.L8(ZQ)
UNNAMED_5_ICMT41K256M16_I196_ZQ: R166.1(N1) U3.L8(ZQ)
UNNAMED_5_ICTPS51206_I120_S3: R222.2(N2) U14.7(S3)
UNNAMED_5_ICTPS51206_I120_S5: R221.2(N2) U14.9(S5)
UNNAMED_5_ICTPS51206_I120_VLDOI: R6.2(N2) U14.2(VLDOIN)
UNNAMED_5_ICTPS51206_I120_VTTSN: R161.2(N2) U14.5(VTTSNS)
UNNAMED_5_ICXC7Z035_I146_PSDD_1: R135.1(N1) U1.W21(PS_DDR_VRP_502)
UNNAMED_5_ICXC7Z035_I146_PSDDRV: R134.1(N1) U1.V21(PS_DDR_VRN_502)
UNNAMED_6_CAP_I20_N1: C178.1(N1) C251.1(N1) L12.2(N2) U1.M18(VCCPLL)
UNNAMED_6_CAP_I222_N1: C189.1(N1) C190.1(N1) E1.2(N2) U1.M14(VCCADC_0)
UNNAMED_6_CAP_I222_N2: C189.2(N2) C190.2(N2) E12.2(N2) U1.M13(GNDADC_0) U1.N13(VREFN_0) U1.P14(VREFP_0)
UNNAMED_6_DIOLED_I280_N: D4.C(N) R172.1(N1)
UNNAMED_6_ICXC7Z035_I180_CFGBVS: R167.2(N2) U1.T7(CFGBVS_0)
UNNAMED_6_ICXC7Z035_I180_PROGRA: R169.1(N1) U1.V9(PROGRAM_B_0)
UNNAMED_7_CAP_I123_N2: C47.2(N2) U1.R6(MGTREFCLK0P_112)
UNNAMED_7_CAP_I124_N2: C48.2(N2) U1.U5(MGTREFCLK1N_112)
UNNAMED_7_CAP_I125_N2: C45.2(N2) U1.R5(MGTREFCLK0N_112)
UNNAMED_7_CAP_I126_N2: C46.2(N2) U1.U6(MGTREFCLK1P_112)
UNNAMED_7_ICXC7Z035_I94_MGTRREF: R10.2(N2) U1.AB8(MGTRREF_112)
UNNAMED_8_AD9361_I22_RBIAS: R125.1(N1) U17.L4(RBIAS)
UNNAMED_8_AD9361_I22_RXVCOLDOOU: C13.1(N1) R124.1(N1) U17.G2(RX_VCO_LDO_OUT) U17.G3(VDDA1P1_RX_VCO)
UNNAMED_8_CAP_I19_N1: C12.1(N1) R124.2(N2)
UNNAMED_8_CAP_I51_N1: C105.1(N1) R123.2(N2)
UNNAMED_8_CAP_I135_N1: C8.1(N1) T1.6(SEC_DOT)
UNNAMED_8_CAP_I136_N1: C9.1(N1) T1.4(SEC)
UNNAMED_8_CAP_I137_N1: C10.1(N1) T3.6(SEC_DOT)
UNNAMED_8_CAP_I138_N1: C11.1(N1) T3.4(SEC)
UNNAMED_8_CAP_I199_N1: C7.1(N1) R2.2(N2)
UNNAMED_8_CAP_I200_N1: C6.1(N1) R1.2(N2)
UNNAMED_8_CAP_I209_N2: C25.2(N2) T5.6(SEC_DOT)
UNNAMED_8_CAP_I210_N2: C26.2(N2) T5.4(SEC)
UNNAMED_8_CAP_I220_N2: C32.2(N2) T7.6(SEC_DOT)
UNNAMED_8_CAP_I221_N2: C33.2(N2) T7.4(SEC)
UNNAMED_8_CAP_I263_N1: C53.1(N1) T4.6(SEC_DOT)
UNNAMED_8_CAP_I264_N1: C56.1(N1) T4.4(SEC)
UNNAMED_8_CAP_I265_N1: C51.1(N1) T2.6(SEC_DOT)
UNNAMED_8_CAP_I266_N1: C52.1(N1) T2.4(SEC)
UNNAMED_8_CAP_I272_N2: C29.2(N2) T6.6(SEC_DOT)
UNNAMED_8_CAP_I273_N2: C30.2(N2) T6.4(SEC)
UNNAMED_8_CAP_I284_N2: C35.2(N2) T8.4(SEC)
UNNAMED_8_CAP_I285_N2: C34.2(N2) T8.6(SEC_DOT)
UNNAMED_8_CNBNC3P_I244_CNTR: RX1A.1(CNTR) T1.3(PRI_DOT)
UNNAMED_8_CNBNC3P_I245_CNTR: RX2A.1(CNTR) T3.3(PRI_DOT)
UNNAMED_8_CNBNC3P_I246_CNTR: T5.3(PRI_DOT) TX1A.1(CNTR)
UNNAMED_8_CNBNC3P_I247_CNTR: T7.3(PRI_DOT) TX2A.1(CNTR)
UNNAMED_8_CNBNC3P_I254_CNTR: RX1B.1(CNTR) T2.3(PRI_DOT)
UNNAMED_8_CNBNC3P_I261_CNTR: RX2B.1(CNTR) T4.3(PRI_DOT)
UNNAMED_8_CNBNC3P_I278_CNTR: T6.3(PRI_DOT) TX1B.1(CNTR)
UNNAMED_8_CNBNC3P_I290_CNTR: T8.3(PRI_DOT) TX2B.1(CNTR)
UNNAMED_8_CNBNC3P_I292_CNTR: R1.1(N1) R101.1(N1) TXM1.1(CNTR)
UNNAMED_8_CNBNC3P_I294_CNTR: R2.1(N1) R102.1(N1) TXM2.1(CNTR)
UNNAMED_8_ICFXL4T245_I328_T: R59.1(N1) U22.6(T/R_N)
UNNAMED_9_ADP238X_I1088_BST: C253.2(N2) U18.15(BST)
UNNAMED_9_ADP238X_I1088_COMP: C255.1(N1) C256.1(N1) U18.1(COMP)
UNNAMED_9_ADP238X_I1088_RT: R78.1(N1) U18.22(RT)
UNNAMED_9_ADP238X_I1088_SS: C252.1(N1) U18.24(SS)
UNNAMED_9_ADP238X_I1088_SW1: C253.1(N1) L301.1(N1) U18.5(SW1) U18.6(SW2) U18.7(SW3) U18.14(SW4) U18.PAD2(SW5)
UNNAMED_9_ADP238X_I1088_VREG: C254.1(N1) U18.3(VREG)
UNNAMED_9_ADP1754_I1076_SS: C311.1(N1) U19.7(SS)
UNNAMED_9_ADP1754_I1077_SS: C340.1(N1) U20.7(SS)
UNNAMED_9_CAP_I1113_N1: C257.1(N1) C305.1(N1) L13.1(N1) L301.2(N2)
UNNAMED_9_CAP_I1113_N2: C257.2(N2) R80.1(N1)
UNNAMED_9_CAP_I1135_N2: C255.2(N2) R79.1(N1)
UNNAMED_9_DIOLED_I1083_N: D3.C(N) R113.1(N1)
UNNAMED_9_RES_I987_N2: Q14.3(D) R113.2(N2)
UNNAMED_10_AD7291_I1_AS0: R65.2(N2) R66.1(N1) U24.11(AS0)
UNNAMED_10_AD7291_I1_AS1: R63.2(N2) R64.1(N1) U24.13(AS1)
UNNAMED_10_AD7291_I1_DCAP: C133.1(N1) U24.8(DCAP)
UNNAMED_10_AD7291_I1_VIN3: R67.2(N2) R68.1(N1) U24.1(VIN3)
UNNAMED_10_AD7291_I1_VIN6: R61.2(N2) R62.1(N1) U24.4(VIN6)
UNNAMED_10_AD7291_I1_VREF: C158.1(N1) U24.7(VREF)
UNNAMED_10_ADG772_I61_D1: C216.1(N1) U5.2(D1)
UNNAMED_10_ADG772_I61_IN1: Q6.3(D) R33.2(N2) U5.4(IN1)
UNNAMED_10_ADG772_I61_S1B: U5.3(S1B) Y4.3(OUT)
UNNAMED_10_ADM7160_I78_VOUT: C5.1(N1) C113.1(N1) R55.1(N1) U8.5(VOUT) Y4.4(VDD)
UNNAMED_10_CN10PAB_I48_N5A: P1.A5(N5A) P1.B5(N5B)
UNNAMED_10_DIOLED_I52_N: DS1.C(N) R75.1(N1)
UNNAMED_10_RES_I53_N2: R54.2(N2) R55.2(N2) Y4.1(E/D)
USB_ID: JX3.63(N7) U15.23(ID)
USB_OTG_CPEN: JX3.70(N10) U15.17(CPEN)
USB_OTG_N: JX3.69(N10) U15.19(DM) U16.6(I/O4)
USB_OTG_P: JX3.67(N9) U15.18(DP) U16.1(I/O1)
USB_VBUS_OTG: JX3.68(N9) U15.22(VBUS)
V_0_N: JX3.3(N2) U1.P13(VN_0)
V_0_P: JX3.1(N1) U1.N14(VP_0)
VH: C247.1(N1) D1.3(N3) U7.10(VH) U23.1(VIN) U23.3(EN)
VTT_0P75: C79.1(N1) C80.1(N1) C101.1(N1) R136.2(N2) R137.2(N2) R138.2(N2) R139.2(N2) R140.2(N2) R141.2(N2) R143.2(N2) R144.2(N2) R145.2(N2) R146.2(N2) R147.2(N2) R148.2(N2) R149.2(N2) R150.2(N2) R151.2(N2) R152.2(N2) R153.2(N2) R154.2(N2) R155.2(N2) R156.2(N2) R159.2(N2) R160.2(N2) R161.1(N1) R162.2(N2) R163.2(N2) U14.3(VTT) U24.2(VIN4)
VTTVREF: C76.1(N1) C77.1(N1) C81.1(N1) C84.1(N1) C102.1(N1) C103.1(N1) C122.2(N2) C123.2(N2) U1.K21(PS_DDR_VREF0_502) U1.M21(PS_DDR_VREF1_502) U2.H1(VREFDQ) U2.M8(VREFCA) U3.H1(VREFDQ) U3.M8(VREFCA) U14.6(VTTREF) U24.3(VIN5)

Pads without a net: JX2 100; JX4 81 82; U1 AA5 AA6 AC1 AC2 AE1 AE2 AF3 AF4 AF7 AF8 W5 W6; U2 J1 J9 L1 L9 M7; U3 J1 J9 L1 L9 M7; U6 4 7; U7 19 20; U8 4; U9 4; U10 9 12 29 31 32; U13 A2 A3 A5 B1 B5 C1 C3 C5 D1 D5 E1 E2 E3 E4 E5; U15 12 15 16 25; U16 3 4; U17 A3 G1 M3 M11; U18 23; U19 8; U20 8; U21 5; U24 12

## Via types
v1: diameter 0.381, hole 0.203, TOP to BOTTOM, 1845 vias
v2: diameter 0.254, hole 0.127, TOP to L2_GND, 944 vias
v3: diameter 0.381, hole 0.203, L2_GND to L19_GND, 168 vias
v4: diameter 0.203, hole 0.127, L19_GND to BOTTOM, 239 vias
v5: diameter 0.508, hole 0.254, TOP to BOTTOM, 158 vias
v6: diameter 0.305, hole 0.152, TOP to BOTTOM, 125 vias

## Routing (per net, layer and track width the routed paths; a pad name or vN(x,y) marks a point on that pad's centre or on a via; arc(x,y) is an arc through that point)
0.95V: length 48.4
  TOP w0.203: U1.V16 v1(29.22,27.59) ; U1.L11 v1(37.22,33.59) ; U1.U13 v1(30.22,31.59) ; U1.L15 v1(37.22,28.59) ; U1.T12 v1(31.22,32.59) ; U1.T16 v1(31.22,27.59) ; U1.P16 v1(33.22,27.59) ; U1.N11 v1(35.22,33.59) ; U1.N15 v1(35.22,28.59) ; U1.M16 v1(36.22,27.59) ; U1.T14 v1(31.22,29.59) ; U1.P12 v1(33.22,32.59) ; U1.U11 v1(30.22,33.59) ; U1.R11 v1(32.22,33.59) ; U1.M12 v1(36.22,32.59) ; U1.L13 v1(37.22,31.59) ; U1.U15 v1(30.22,28.59) ; U1.R15 v1(32.22,28.59)
  TOP w0.254: R303.2 v2(24.5,10.46)
  TOP w0.305: U7.1 7.37,39.99 6.53,39.99 v1(5.51,38.97)
  TOP w0.406: C44.P 76.76,2.27 76.38,1.89 v1(75.11,1.89) ; C44.P 76.76,3.28 75.87,4.17 v1(75.11,4.17) ; C44.P 76.76,2.9 ; v1(75.11,3.41) 76.25,3.41 76.76,2.9 ; C258.1 42.22,2.39 v1(42.09,2.39) v1(41.45,2.39) ; 76.76,2.9 76.51,2.9 76.22,2.61 75.14,2.61 v1(75.11,2.65)
  L2_GND w0.254: v2(24.5,10.46) v3(23.99,10.46)
  BOTTOM w0.305: C149.1 33.2,30.84 32.69,31.35 32.69,32.06 v1(33.22,32.59) ; C140.1 37.37,28.43 v1(37.22,28.59) ; v1(30.22,31.59) 30.02,31.4 C142.1 29.26,30.59 C150.1 ; v1(31.22,32.59) 31.25,32.62 C151.1 ; v1(35.22,28.59) 34.49,29.32 C148.1 ; C156.1 v1(26.21,30.59)
  BOTTOM w0.406: C44.P 76.76,2.9 ; v1(41.45,2.39) v1(42.09,2.39) 42.22,2.39 C258.1 41.84,1.89 41.45,2.27 v1(41.45,2.39)
  BOTTOM w0.508: 76.38,2.9 76.25,2.9 76,2.65 v1(75.11,2.65) ; 76.38,2.9 75.87,3.41 v1(75.11,3.41) ; 76.38,2.9 76.76,2.9 ; C152.1 37.14,31.51 v1(37.22,31.59) ; v1(51.49,12.81) 51.07,13.23 C194.1 ; v1(75.11,4.17) 76.51,4.17 76.76,3.92 76.76,2.91 76.76,2.9 ; 76.76,2.9 75.74,1.89 v1(75.11,1.89) ; C195.1 57.55,14.8 v1(58.09,15.35)
  vias: v1(8.18,6.97) v1(8.18,6.33) v1(8.56,5.7) v1(8.56,5.06) v1(8.56,4.43) v1(8.56,3.79) v1(9.2,4.43) v1(9.83,4.43) v3(0.94,21.95) v3(0.94,21.32) v3(0.94,20.68) v3(0.94,20.05) v3(0.94,19.41) v3(1.07,38.97) v3(1.07,37.57) v3(1.07,36.81) v3(1.07,14.33) v3(1.07,13.7) v3(1.07,13.06) v3(1.07,12.43) v3(1.07,11.79) v3(1.07,11.16) v3(1.07,10.52) v3(1.45,27.67) v3(1.45,26.78) v3(1.58,39.48) v3(1.58,31.1) v3(1.7,29.7) v3(2.21,13.06) v3(2.21,12.43) v3(2.21,11.79) v3(2.21,11.16) v3(2.21,10.52) v3(3.99,37.57) v3(5.39,22.08) v3(58.35,16.87) v3(58.35,15.98) v3(59.87,17.25) v3(59.87,16.75) v3(62.16,17.89) v3(62.16,17.25) v3(62.79,17.63) v3(63.81,17.89) v3(63.81,17.25) v3(64.44,17.89) v3(64.44,17.25)
1.0V: length 117.7
  TOP w0.254: C67.1 58.38,14.17 59.23,13.32 59.25,13.32 59.3,13.26 59.44,13.26 ; U4.10 59.75,11.16 59.41,11.49 59.38,11.49 59.16,11.72 59.16,12.92 59.26,13.02 59.26,13.09 59.44,13.26 ; 59.44,13.26 v1(59.46,13.26)
  TOP w0.305: U7.2 8.08,39.25 7.74,38.91 7.35,38.91 7.04,39.22 6.4,39.22 6.02,38.84 6.02,38.07 v1(5.51,37.56)
  TOP w0.508: v1(53.14,12.68) E4.1 ; v1(53.14,12.68) 53.65,13.19 55.19,13.19 L5.2 ; v1(53.14,12.68) 53.9,12.68 v1(54.15,12.43)
  L4_SIG w0.254: v3(58.85,2.39) 57.2,0.74 33.58,0.74 33.07,1.25 32.44,1.25 31.68,0.49 19.74,0.49 17.83,2.39 8.56,2.39 7.55,3.41 7.55,6.59 7.16,6.97 7.16,7.98 6.66,8.49 6.66,13.95 5.89,14.71 v3(5.89,16.36)
  L6_SIG w0.508: v3(5.89,16.36) 6.66,16.36 7.8,17.51 7.8,21.95 6.66,23.1 5.77,23.1 5.39,23.48 5.39,35.8 5.51,35.92 v1(5.51,37.56)
  L7_SIG w0.254: v1(59.46,13.26) 59.11,12.91 59.11,11.41 58.73,11.03 58.73,8.49 58.6,8.36 58.6,5.82 58.85,5.57 v3(58.85,2.39)
  BOTTOM w0.381: v1(53.14,12.68) 53.9,12.68 v1(54.15,12.43)
  BOTTOM w0.406: v1(59.46,13.26) 59.35,13.38 R23.2
  vias: v1(58.47,14.21) v1(58.98,14.21)
1.8V: length 62.4
  TOP w0.254: v1(77.14,6.08) 77.59,5.63 C310.1 ; C347.1 75.55,7.79 v1(75.87,7.47)
  TOP w0.305: U7.6 10.08,39.35 10.09,39.35 v1(10.09,39.15) ; U4.22 60.25,6.46 60.76,5.95 60.76,5.19 v1(60.89,5.06) 60.76,4.93 v1(60.76,4.46)
  TOP w0.381: v1(75.87,8.24) 76.05,8.42 U20.15 ; v1(77.14,6.08) 77.56,6.5 U20.1 ; U19.15 66.4,8.42 v1(66.09,8.11) 66.43,7.77 U19.16 ; v1(68.76,5.06) 68.56,5.26 U19.2 ; v1(78.03,6.08) 78.21,6.26 U20.2 ; U19.3 69.21,5.5 v1(69.52,5.19) ; v1(75.87,7.47) 76.17,7.77 U20.16 ; v1(67.93,5.12) C318.1 67.91,5.85 U19.1 ; U20.3 v1(78.86,6.01) ; E10.1 v1(74.73,11.67)
  TOP w0.406: 65.08,6.84 65.08,7.09 v1(66.09,8.11)
  TOP w0.508: v1(14.4,12.3) 14.4,12.74 E9.1 ; C362.1 v1(74.69,6.37) ; E14.1 30.72,5.06 30.02,5.06 v1(29.77,5.32)
  L4_SIG w0.381: v1(10.09,39.15) 10.54,39.15
  L4_SIG w0.508: 10.54,39.15 12.5,37.19 12.5,35.04 12.46,35.01 12.46,34.06 12.88,33.64 12.88,26.28 15.55,23.61 15.55,18.79 14.65,17.89 13.39,17.89 13.13,17.63 13.13,14.71 14.4,13.44 v1(14.4,12.3)
  L19_GND w0.406: 63.97,13.66 63.88,13.57 62.66,13.57 ; 63.97,13.66 v3(64.31,13.32) v4(63.17,13.32) v4(62.66,13.32) 62.66,13.57 ; 63.97,13.66 v3(63.97,13.86) 63.93,13.82 v4(63.17,13.82) v4(62.66,13.82) 62.66,13.57
  BOTTOM w0.406: v1(60.76,4.46) 60.76,3.68 60.49,3.41 C69.1 59.7,2.56 v1(59.74,2.52)
  vias: v1(60.5,2.52) v1(60.76,3.28) v1(61.27,2.52)
1.8V_EN: length 121.2
  TOP w0.14: U7.23 11.08,46.44 12.24,47.61 14.28,47.61 14.4,47.73 v1(14.53,47.73) ; v2(62.03,6.46) 61.9,6.33 61.52,6.33 61.25,6.61 U4.24
  L2_GND w0.203: v2(62.03,6.46) v3(61.52,6.46)
  L18_SIG w0.095: v3(61.52,6.46) 62.41,5.57 62.41,2.78 60.41,0.77 33.68,0.77 33.33,1.12 32.15,1.12 31.8,0.77 19.33,0.77 14.91,5.19 11.86,5.19 9.07,7.98 7.04,7.98 6.66,8.36 6.66,9.38 2.97,13.06 2.97,17.89 2.63,18.23 2.63,20.72 3.61,21.7 3.61,30.08 4.75,31.22 4.75,39.86 3.61,41 3.61,43.29 4.62,44.3 7.29,44.3 8.94,45.96 12.75,45.96 v1(14.53,47.73)
1.35V: length 77.3
  TOP w0.254: U4.9 v2(60.25,11.53)
  TOP w0.305: v1(9.56,39.11) 9.58,39.13 U7.5
  TOP w0.406: 62.92,14.71 63.08,14.55 C68.1
  TOP w0.508: v1(51.61,4.68) 51.42,4.49 E2.1 ; v1(47.3,9.38) 47.8,9.38 48.44,10.01 E3.1 ; R24.2 v1(53.3,14.55)
  L2_GND w0.254: v2(60.25,11.53) v3(59.75,11.53)
  L4_SIG w0.305: 8.95,39.11 v1(9.56,39.11)
  L4_SIG w0.406: 60.12,13.1 60.1,13.1 59.76,12.76 59.76,12.73 59.7,12.68 59.7,11.99 59.75,11.95
  L4_SIG w0.508: v3(31.68,1.63) 31.42,1.38 29.01,1.38 28.65,1.02 27.34,1.02 26.21,2.14 25.71,2.14 25.29,2.56 25.23,2.56 24.63,3.16 16.94,3.16 14.78,5.32 11.36,5.32 8.18,8.49 8.18,11.79 7.67,12.3 7.67,18.4 8.31,19.03 8.31,38.46 8.95,39.11 ; v1(59.74,14.21) 60.12,13.82 60.12,13.1 ; 59.75,11.95 v3(59.75,11.53)
  L17_SIG w0.406: v1(47.3,9.38) 47.68,9.38 48.06,9 48.06,7.6 48.82,6.84 50.73,6.84 51.61,5.95 v1(51.61,4.68)
  vias: v1(61.52,14.46) v1(62.03,14.46)
3.3V: length 56.6
  TOP w0.254: C188.1 75.36,59.42 v1(75.74,59.04)
  TOP w0.305: U5.6 79.32,57.91 79.55,58.15 80.32,58.15 80.57,58.4 ; 37.01,53.83 v1(36.88,53.7) 37.14,53.44 U9.2 ; 37.01,53.83 37.01,54.72 36.03,55.7 C38.1 ; 37.01,53.83 37.12,53.94 U9.1
  TOP w0.406: v1(1.58,38.46) 2.21,39.1 R34.1
  TOP w0.508: E16.1 15.93,15.16 v1(15.93,15.98) ; E15.1 11.99,18.02 11.74,18.27 10.72,18.27 v1(10.59,18.4) ; v5(80.57,59.29) R33.1 ; E8.1 33.14,58.72 32.69,58.27 v1(32.69,57.89) ; E7.1 v1(26.47,59.54)
  L14_SIG w0.508: v1(10.59,18.4) 10.72,18.27 11.36,18.27 12.75,16.87 12.75,15.98 13.51,15.22 15.17,15.22 v1(15.93,15.98)
  L17_SIG w0.508: v1(10.59,18.4) 10.38,18.61 10.38,19.63 9.96,20.05 8.82,20.05 8.05,20.81 8.05,22.21 7.42,22.84 5.26,22.84 4.75,23.35 4.75,28.18 3.1,29.83 3.1,36.94 v1(1.58,38.46)
  BOTTOM w0.254: v1(76.76,56.62) 77.28,57.14 U6.5 ; U6.8 77.28,58.64 v1(77.01,58.91)
  BOTTOM w0.406: U8.3 75.26,55.03 C260.1 74.98,54 v1(74.69,53.7) 74.98,53.7 v1(75.49,53.19) 75.88,53.19 v1(75.94,53.13) U8.1
3.3V_EN: length 40.7
  TOP w0.14: v1(9.7,48.37) 8.84,47.5 8.84,46.83 9.08,46.58 U7.27 ; U9.5 40.81,52.44 41.07,52.18 41.07,49.77 v1(41.2,49.64)
  L6_SIG w0.095: v1(9.7,48.37) 11.23,48.37 13.39,46.21 14.28,46.21 15.04,45.45 17.45,45.45 18.34,46.34 29.39,46.34 30.53,47.48 35.74,47.48 37.39,49.13 40.69,49.13 v1(41.2,49.64)
3.3V_SEQ: length 5.2
  TOP w0.14: R35.1 R34.2 3.93,39.54 v1(3.99,39.61) ; U7.38 v1(5.53,41.53)
  L17_SIG w0.095: v1(3.99,39.61) 5.53,41.15 v1(5.53,41.53)
3V3_I2C: length 168.1
  TOP w0.203: U23.4 58.79,55.17 58.35,55.61 57.14,55.61 57.01,55.73
  TOP w0.254: v1(15.17,38.46) 14.91,38.21 R71.2 ; v5(34.6,57.51) 33.45,57.51 32.6,56.66 32.6,56.62 D3.A
  TOP w0.305: C248.1 57.01,56.52 57.01,55.38 56.89,55.25 U23.5
  TOP w0.406: R69.2 v1(9.83,38.59)
  TOP w0.508: v5(57.11,57.35) C248.1
  L3_SIG w0.508: v1(6.28,27.03) 5.39,27.03 3.23,29.19 3.23,35.29 2.34,36.18 v1(2.34,39.73)
  L4_SIG w0.508: v5(34.6,57.51) 34.6,58.78 ; 34.6,58.78 30.28,58.78 29.64,58.15 26.14,58.15 25.5,57.51 22.79,57.51 21.26,59.04 15.93,59.04 14.28,57.39 11.48,57.39 2.85,48.75 2.85,40.24 v1(2.34,39.73) ; 34.6,58.78 35.23,59.42 43.11,59.42 44.25,58.27 45.52,58.27 46.14,57.65 46.68,57.65 47.04,58.02 47.3,58.02 48.06,58.78 55.04,58.78 v1(56.48,57.35) v5(57.11,57.35)
  L6_SIG w0.406: 78.54,48.24 77.65,48.24 77.27,48.62 75.11,48.62 74.73,48.24 v1(74.22,48.24) 73.84,48.24 73.59,48.5 73.59,50.27 72.57,51.29 63.93,51.29 62.28,52.94 62.28,54.21 61.9,54.59 ; 78.54,48.24 v1(79.55,49.26) ; 78.54,48.24 78.67,48.24 v3(79.17,47.73)
  L6_SIG w0.508: 61.9,54.59 59.87,54.59 v5(57.11,57.35) v1(56.48,57.35)
  L14_SIG w0.406: v1(15.17,38.46) 14.66,38.97 11.1,38.97 10.72,38.59 v1(9.83,38.59) 8.05,38.59 7.04,39.61 4.88,39.61 4.24,40.24 2.85,40.24 v1(2.34,39.73)
  L15_SIG w0.406: v1(74.22,48.24) 74.22,47.73 74.09,47.61 74.09,43.16 73.71,42.78 73.71,41.13 v3(74.09,40.75)
  L19_GND w0.305: v3(79.17,47.73) 79.17,46.97 78.91,46.71 v4(78.91,45.44)
  L19_GND w0.406: v3(79.17,47.73) 78.67,48.24 v4(77.27,48.24) ; v4(73.33,46.21) 73.33,46.84 74.22,47.73 v1(74.22,48.24) ; v3(74.09,40.75) 74.47,40.37 v4(74.47,40.24)
  BOTTOM w0.305: U24.10 73.6,45.94 v4(73.33,46.21) ; v1(6.28,27.03) 5.96,27.35 C244.2 4.96,26.42 U21.8
  BOTTOM w0.33: U24.16 78.81,45.94 78.91,45.84 v4(78.91,45.44) U24.17
  BOTTOM w0.406: C134.1 79.21,48.91 v1(79.55,49.26) ; R63.1 v4(77.27,48.24) ; C124.1 73.08,46.46 v4(73.33,46.21) ; R61.1 74.92,40.68 v4(74.47,40.24) ; v1(74.22,48.24) R65.1
  BOTTOM w0.508: R51.1 R52.1 v1(2.34,39.73)
GND: length 788.6
  TOP w0.127: v2(73.16,41.3) v2(73.76,41.5)
  TOP w0.14: 66,24.89 v6(66,24.83) ; v6(66,31.29) U17.H6 ; 67.6,24.89 67.6,24.84 v6(67.6,24.84) ; v6(68.4,31.29) U17.H3
  TOP w0.203: v6(65.2,31.29) U17.H7 ; U1.V5 v1(29.22,39.59) ; C122.1 v2(56.71,42.65)
  TOP w0.254: R79.2 26.47,9.17 26.47,9.13 v2(26.47,8.74) ; R40.2 v2(4.12,43.67) ; C115.2 49.52,44.37 v2(49.58,44.3) ; v5(9.45,44.18) v2(8.56,44.18) 8.43,44.18 7.58,45.03 U7.31 ; 49.84,31.73 v2(49.2,31.73) ; v6(70,26.49) U17.C1 ; U22.7 56.94,32.12 v2(57.08,31.99) ; U13.B3 v2(68.12,56.62) ; U1.AC6 v1(24.22,37.59) U1.AD7 ; v1(78.22,4.81) C310.2 ; U17.A12 60.42,25.67 60.42,25.72 ; v6(60.4,27.29) U17.D12 ; v6(63.6,26.49) U17.C8 ; C256.2 v2(23.86,9.43) ; R101.2 v1(70.54,40.11) ; U22.9 55.95,32.48 v2(56.44,31.99) 56.44,31.99 U22.8 ; v6(70,25.69) U17.B1 ; v6(69.2,32.89) U17.K2 ; C188.2 74.35,59.42 v5(73.97,59.8) ; R102.2 83.75,19.29 ; R38.2 v2(4.12,44.69) ; v6(70,33.69) U17.L1 ; U1.AE5 v1(23.22,39.59) U1.AD4 ; U7.40 7.58,40.53 v2(8.05,41) ; v6(69.2,25.69) U17.B2 ; v6(60.4,32.89) U17.K12 ; v6(62.8,26.49) U17.C9 ; v6(68.4,28.89) U17.F3 ; U1.AD3 v1(24.22,41.59) ; U5.10 76.63,57.51 76.51,57.64 v1(76.25,57.64) ; v6(62,26.49) U17.C10 ; v6(70,32.89) U17.K1 ; v6(60.4,30.49) U17.G12 ; U1.AD8 v1(23.22,35.59) ; v6(69.2,26.49) U17.C2 ; v2(23.29,11.41) 23.55,11.16 R302.1 ; C116.2 v2(57.96,47.86) ; U18.PAD1 22.91,7.11 22.91,7.86 22.66,8.11 U18.4 ; v6(69.2,31.29) U17.H2 ; U17.A4 67.6,24.89 ; v6(69.2,33.69) U17.L2 ; v6(65.2,27.29) U17.C7 ; v6(68.4,33.69) U17.L3 ; U1.AC5 v1(25.22,39.59) ; v6(60.4,26.49) U17.C12 ; C343.2 v1(74.35,10.14) ; v6(61.2,26.49) U17.C11 ; U17.A6 66,24.89 ; v6(67.6,26.49) U17.C4 ; v6(67.6,34.49) U17.M4 ; v6(69.2,32.09) U17.J2 ; U7.11 12.08,40.53 v2(11.86,40.75) 11.58,41.03 U7.12 ; v6(60.4,25.69) 60.42,25.72 ; 60.42,25.72 U17.B12 ; v6(62.8,28.89) U17.F9 ; R133.2 v2(52.49,45.08) ; v6(61.2,28.89) U17.F11 ; U1.AE6 v1(22.22,37.59) ; v6(62,31.29) U17.H10 ; v6(60.4,33.69) U17.L12 ; v6(70,27.29) U17.D1 ; C344.2 v1(74.35,9.38) ; C347.2 v1(74.79,8.43)
  TOP w0.305: U1.AC9 v1(24.22,35.59) ; U1.P9 v1(33.22,35.59) ; U1.P1 v1(33.22,43.59) ; v6(62,33.69) U17.L10 ; U1.AB9 v1(25.22,35.59) ; U4.19 58.75,7.62 ; 58.75,7.62 v1(59.23,8.11) U4.PAD v1(60.25,9.13) 60.75,9.62 U4.5 62.62,9.62 62.87,9.87 ; 58.75,7.62 U4.18 ; U1.Y8 v1(27.22,36.59) U1.AA7 ; M1.GND19 78.63,30.68 v5(79.17,31.22) ; U1.T15 v1(31.22,28.59) ; U1.M9 v1(36.22,35.59) ; U1.AE19 v1(22.22,24.59) ; C65.2 56.09,9.62 U4.14 59.25,9.62 ; U1.V20 v1(29.22,23.59) ; v1(54.41,28.18) 54.66,28.43 C246.2 ; 49.84,58.53 50.22,58.15 v2(50.22,57.64) ; 49.84,58.53 C79.2 ; 49.84,58.53 49.46,58.15 v2(49.46,57.64) ; U1.U18 v1(30.22,25.59) ; U1.A11 v1(47.22,33.59) ; C88.2 v2(58.6,26.14) ; U1.F6 v1(42.22,38.59) ; U11.2 8.55,13.84 v2(8.31,14.08) U11.PAD v2(7.29,15.09) 7.05,15.34 U11.11 7.05,17.52 v5(6.79,17.77) ; U1.P6 v1(33.22,37.59) U1.P7 ; v6(66,34.49) U17.M6 ; 1.83,49.13 1.07,49.89 v1(1.07,50.27) ; 1.83,49.13 C180.2 1.83,47.86 v1(1.58,47.61) ; 1.83,49.13 1.83,50.15 v1(1.7,50.27) ; U1.J7 v1(39.22,37.59) ; U1.U16 v1(30.22,27.59) ; U18.13 21.28,4.41 v1(21.13,4.55) ; U1.AF26 v1(21.22,17.59) ; U1.L12 v1(37.22,32.59) ; C196.2 v2(21.55,57.8) ; C196.2 v2(21.26,57.51) ; C196.2 v2(20.97,57.8) ; U1.A1 v1(47.22,43.59) ; U1.AD9 v1(23.22,35.59) ; C91.2 v2(57.33,15.98) ; U1.T13 v1(31.22,31.59) ; U1.C5 v1(45.22,39.59) ; U1.AA3 v1(26.22,41.59) ; U1.C15 v1(45.22,28.59) ; C103.2 v2(49.33,20.81) ; U1.H20 v1(40.22,23.59) ; U1.AA9 v1(26.22,35.59) ; U1.K14 v1(38.22,29.59) ; 62.87,9.87 C62.2 v1(64.73,10.48) ; 62.87,9.87 63.48,10.48 ; M1.GND22 v2(73.29,38.16) ; U1.M19 v1(36.22,24.59) ; v5(42.34,52.94) 42.34,52.94 U9.6 ; C96.2 v2(49.33,27.16) ; U1.U12 v1(30.22,32.59) ; U9.3 36.51,52.94 v5(36.25,52.69) ; C311.2 v1(73.08,10.4) ; U1.E19 v1(43.22,24.59) ; U1.Y9 v1(27.22,35.59) ; U1.U7 v1(30.22,37.59) ; U1.E9 v1(43.22,35.59) ; C117.2 v2(57.2,37.57) ; U1.AF9 v1(21.22,35.59) ; C118.2 v2(57.46,33.89) ; U1.AE9 v1(22.22,35.59) ; U1.U14 v1(30.22,29.59) ; M1.GND11 v2(57.56,17.15) ; U1.Y1 v1(27.22,43.59) ; U1.Y24 v1(27.22,19.59) ; U1.G13 v1(41.22,31.59) ; R74.2 15.29,40.49 v2(15.67,40.88) ; U1.R3 v1(32.22,41.59) ; U1.M17 v1(36.22,26.59) ; U1.G3 v1(41.22,41.59) ; U1.T17 v1(31.22,26.59) ; R165.2 v2(57.71,22.71) ; U1.AD5 v1(23.22,39.59) ; C92.2 v2(49.33,19.29) ; U1.R16 v1(32.22,27.59) ; M1.GND20 v2(73.29,25.72) ; U1.J17 v1(39.22,26.59) ; U1.R18 v1(32.22,25.59) ; U1.L14 v1(37.22,29.59) ; U1.M15 v1(36.22,28.59) ; T1.5 v2(76.76,40.88) ; U1.AE3 v1(22.22,41.59) ; v2(74.35,52.94) 74.22,52.81 C113.2 ; C38.2 38.41,55.86 39.17,55.1 39.17,53.32 ; C87.2 v2(57.58,23.73) ; U1.AD22 v1(23.22,21.59) ; C337.2 71.87,25.83 v1(72.44,26.4) ; v6(63.6,33.69) U17.L8 ; U1.AA11 v1(26.22,33.59) ; U1.U10 v1(30.22,34.59) ; U1.R12 v1(32.22,32.59) ; U1.T19 v1(31.22,24.59) ; U1.C25 v1(45.22,18.59) ; U1.P17 v1(33.22,26.59) ; U1.H10 v1(40.22,34.59) ; C94.2 v2(56.44,23.48) ; U1.P5 U1.P4 v1(33.22,40.59) ; C315.2 65.14,9.19 v1(64.82,9.51) 65.14,9.82 C314.2 ; U1.AA21 v1(26.22,22.59) ; C123.1 v2(57.25,25.71) ; U1.V1 v1(29.22,43.59) ; U1.F26 v1(42.22,17.59) ; U1.F16 v1(42.22,27.59) ; U1.R10 v1(32.22,34.59) ; v6(61.2,33.69) U17.L11 ; v6(62.8,33.69) U17.L9 ; v2(45.14,60.81) 44.38,60.81 44.12,60.56 C81.2 44.06,60.5 43.61,60.94 v2(43.11,60.94) ; U1.T11 v1(31.22,33.59) ; U1.AC15 v1(24.22,28.59) ; v2(72.55,17.15) M1.GND14 v2(74.33,17.15) ; U1.N18 v1(35.22,25.59) ; U1.D2 v1(44.22,42.59) ; U1.D22 v1(44.22,21.59) ; U1.A21 v1(47.22,22.59) ; U1.N10 v1(35.22,34.59) ; U1.V7 v1(29.22,37.59) ; C109.2 v2(49.33,33.64) ; U1.AC7 v1(24.22,37.59) ; v2(57.46,21.06) 57.27,21.25 C95.2 ; U1.B18 v1(46.22,25.59) ; U1.D12 v1(44.22,32.59) ; U1.P22 v1(33.22,21.59) ; U1.W7 v1(28.22,37.59) U1.Y7 ; U18.10 20.5,6.21 v1(20.25,6.46) 20.5,6.71 U18.9 ; U1.AF5 v1(21.22,39.59) ; U1.N16 v1(35.22,27.59) ; C245.2 v1(58.47,28.68) ; U1.M11 v1(36.22,33.59) ; U1.T9 v1(31.22,35.59) ; U1.V13 v1(29.22,31.59) ; U1.L16 v1(37.22,27.59) ; U1.AF1 v1(21.22,43.59) ; v1(56.69,5.7) 56.12,6.27 C66.2 ; U18.11 20.51,5.71 v1(20.25,5.44) 20.48,5.21 U18.12 ; C89.2 v2(57.96,21.19) ; U1.T1 v1(31.22,43.59) ; U1.K24 v1(38.22,19.59) ; U1.W3 v1(28.22,41.59) ; U1.Y14 v1(27.22,29.59) ; C102.2 v2(49.46,37.57) ; C225.2 v2(29.77,11.41) ; U1.P11 v1(33.22,33.59) ; U1.N5 v1(35.22,39.59) ; U1.B8 v1(46.22,36.59) ; v6(64.4,33.69) U17.L7 ; U1.AE7 v1(22.22,37.59) ; U1.U3 v1(30.22,41.59) ; U1.P15 v1(33.22,28.59) ; U1.AC3 v1(24.22,41.59) ; U1.AB1 v1(25.22,43.59) ; U1.T26 v1(31.22,17.59) ; U1.V17 v1(29.22,26.59) ; U18.8 v1(20.26,7.21) ; C364.2 v2(17.96,46.21) ; U1.N25 v1(35.22,18.59) ; U17.F7 v1(65.2,29.7) ; U1.L18 v1(37.22,25.59) ; U1.U23 v1(30.22,20.59) ; U1.AD1 v1(23.22,43.59) ; U1.P2 v1(33.22,42.59) ; U1.L21 v1(37.22,22.59) ; C112.2 v2(49.01,42.72) ; U1.P3 v1(33.22,41.59) ; U1.K4 v1(38.22,40.59) ; U1.L10 v1(37.22,34.59) ; U1.T5 v1(31.22,39.59) ; U1.AB5 v1(25.22,39.59) ; U1.AC25 v1(24.22,18.59) ; R35.2 v2(2.85,38.34) ; C97.2 v2(49.33,25.64) ; U1.L1 v1(37.22,43.59) ; U1.G23 v1(41.22,20.59) ; U1.AB18 v1(25.22,25.59) ; U1.AF16 v1(21.22,27.59) ; U1.R7 v1(32.22,37.59) ; U1.P19 v1(33.22,24.59) ; U1.N12 v1(35.22,32.59) ; U1.Y5 v1(27.22,39.59) ; U1.AD12 v1(23.22,32.59)
  TOP w0.381: U19.6 69.39,8.42 69.01,8.8 v1(69.01,8.87) v1(68.51,8.87) ; C318.2 67.13,5.61 v1(67.13,5.74) ; C340.2 81.28,8.43 v1(81.28,8.42) U20.6
  TOP w0.508: v2(53.27,39.36) M1.GND6 v2(53.27,41.51) ; J3.GND2 16.05,22.21 v1(16.82,21.44) ; v1(84.63,3.92) 83.75,3.92 82.85,3.03 C44.N ; C59.2 v1(11.14,10.23) ; C68.2 63.81,10.87 63.43,10.48 C62.2 ; v2(61.14,44.22) M1.GND4 v2(63.04,44.22) ; v5(58.2,59.37) 57.44,59.37 57.06,58.99 ; v5(92.82,42.83) TXM1.3 v2(89.91,42.83) ; v5(89.91,21.24) RX2A.3 v5(92.82,21.24) ; T4.5 v2(76.89,27.29) ; v5(94.99,41.33) RX1A.2 v2(97.92,41.33) ; 57.06,58.99 57.06,58.36 57.31,58.1 v5(58.2,58.1) ; 57.06,58.99 57.08,58.97 C100.2 ; R80.2 v1(15.93,1.12) ; T4.2 v2(77.65,27.29) ; v5(92.82,51.72) TX1B.3 v5(89.91,51.72) ; v5(83.49,39.99) 82.86,39.35 81.84,39.35 81.57,39.08 M1.GND18 ; C41.2 v1(7.16,9.25) ; v1(71.81,48.37) 72.23,48.79 C5.2 ; v2(53.27,36.93) M1.GND7 v2(53.27,34.66) ; T7.2 v2(71.17,20.3) ; Y1.2 47.76,7.41 48.38,7.41 v1(48.82,7.86) 49.58,8.62 ; C49.2 v5(17.71,14.59) ; v2(89.91,45.78) TXM1.2 v5(92.84,45.78) ; v1(46.79,2.27) v1(46.15,2.27) ; v1(46.15,2.27) 45.9,2.27 C258.2 45.77,1.89 v1(46.15,2.27) ; 49.58,8.62 C138.2 ; 49.58,8.62 49.07,8.62 v1(48.69,9) ; C44.N 83.36,2.39 v1(84.63,2.39) ; C44.N 83.24,2.9 83.49,3.16 v1(84.63,3.16) ; C44.N 82.85,2.4 83.62,1.63 v1(84.63,1.63) ; SW1.2A v1(39.93,2.27) ; Q1.2 34.09,8.41 34.09,9.01 v1(34.08,9.01) ; J3.GND3 15.95,29.68 16.92,28.71 16.92,28.7 v1(16.97,28.65) ; v2(89.91,36.89) RX1B.2 v5(92.84,36.89) ; v5(84.25,59.8) 84.61,59.44 Q6.2 ; C312.2 v1(70.25,15.18) ; T1.2 v2(77.52,40.88) ; Q2.2 v5(12.6,58.88) ; v5(10.85,16.87) 11.36,16.36 C54.2 C55.2 ; v5(97.9,47.28) TX1A.3 94.99,47.28 ; v5(94.99,38.39) RX1A.3 v2(97.9,38.39) ; v2(53.27,32.12) M1.GND8 v2(53.27,29.83) ; C120.2 41.58,58.02 v5(41.58,57.51) 41.58,57.13 42.31,56.41 C36.2 ; C165.2 v2(58.27,35.77) ; v5(83.75,23.1) 83.41,22.76 M1.GND16 ; C50.2 27.17,10.78 v1(27.67,10.27) ; T8.2 v2(62.92,18.14) ; v2(57.96,11.7) 57.96,12.21 C67.2 ; v5(94.99,16.8) TXM2.3 v5(97.9,16.8) ; v1(57.33,5.19) 57.71,4.81 C61.2 ; v2(33.25,51.75) Q14.2 33.25,49.84 v2(33.45,49.64) ; C106.2 60.63,46.59 v2(61.16,46.59) ; v1(54.41,8.62) C139.2 v1(51.61,8.62) C138.2 ; C247.2 58.94,49.68 v1(59.36,49.26) ; C172.2 v5(48.19,46.97) ; T3.1 v2(78.92,19.16) ; C39.2 v1(47.42,3.92) ; C86.2 v2(57.84,18.27) ; C248.2 58.82,56.97 v5(59.36,57.51) ; C191.2 50.64,9.04 C138.2 ; v2(77.78,44.22) M1.GND1 v2(79.94,44.22) ; v2(66.6,44.22) M1.GND3 v2(68.76,44.22) ; v5(94.99,10.85) TX2B.2 v5(97.92,10.85) ; C78.2 17.2,19.54 v1(16.82,19.92) ; v5(92.82,12.35) TX2A.3 v5(89.91,12.35) ; T2.2 v2(77.52,37.07) ; v5(92.82,33.94) RX1B.3 v5(89.91,33.94) ; R13.2 v2(32.31,8.36) ; T4.1 v2(77.65,28.56) ; C203.2 16.07,10.9 v1(16.05,10.92) ; v5(94.99,50.22) TX1A.2 v5(97.92,50.22) ; J3.GND4 3.1,33.76 v1(2.21,34.65) ; 17.24,1.12 17.24,1.86 v1(17.26,1.89) 17.26,2.75 ; T5.5 v5(67.62,39.1) ; C192.2 46.83,15.22 v2(46.53,15.22) ; R176.2 v1(19.23,49.26) ; v1(82.96,31.37) 82.94,31.35 81.97,31.35 81.57,30.95 M1.GND17 ; T5.2 v1(67.62,43.16) ; T3.2 v2(77.65,19.16) ; T7.1 v2(71.17,21.57) ; C209.2 v2(15.17,47.48) ; C218.2 23.04,13.82 v1(23.17,13.7) 23.29,13.82 C73.2 24.56,13.82 v1(24.69,13.7) 24.82,13.82 C217.2 26.09,13.82 v1(26.21,13.7) 26.72,13.7 C63.2 ; 59.25,9.62 v1(59.23,9.63) ; R27.2 19.23,59.54 v1(19.61,59.93) ; C197.2 v5(28.08,57.17) ; C183.2 25.58,57.39 v5(26.21,56.75) ; C320.2 v1(72.44,12.17) ; v5(92.84,24.19) RX2A.2 v5(89.91,24.19) ; v5(94.99,28.63) RX2B.2 v5(97.92,28.63) ; C362.2 v1(72.06,5.44) ; SW1.2B v1(36.12,2.27) ; S4.1 v1(45.04,53.48) ; v1(4.5,22.33) 3.75,21.59 J3.GND1 ; v5(46.28,46.72) 46.03,46.46 46.03,46.21 ; C205.2 v1(1.32,40.75) ; v1(52.19,17.91) 51.62,17.34 C193.2 ; v2(53.27,27.53) M1.GND9 v2(53.27,25.26) ; C107.2 v2(59.11,37.83) ; v1(50.59,19.51) 51.36,20.28 C178.2 ; T3.5 v2(77.65,23.48) ; v1(66.07,43.11) 66.35,42.83 T5.1 ; v5(94.99,25.69) RX2B.3 v5(97.9,25.69) ; v1(15.74,57.19) 16.72,56.21 Y3.2 ; T6.1 v2(59.87,38.72) ; T2.5 v2(77.52,32.62) ; C208.2 14.66,11.67 v1(14.53,11.67) ; v2(53.27,22.84) M1.GND10 v2(53.27,20.56) ; v1(60.76,8.36) 60.5,8.62 v1(60.25,8.74) U4.PAD ; R191.2 v5(44.5,13.44) ; E12.1 v5(27.42,51.61) ; v5(89.91,54.67) TX1B.2 v5(92.84,54.67) ; C224.2 v2(32.44,6.97) ; C226.2 v2(19.36,10.9) ; T7.5 v2(70.16,20.3) ; T2.1 v2(76.25,37.07) ; R14.2 v5(14.02,58.4) ; S1.1 v1(2.89,7.81) ; C313.2 v1(65.62,14.17) ; v5(97.92,19.74) TXM2.2 v5(94.99,19.74) ; T8.5 v2(62.92,22.46) ; R119.2 v2(73.59,51.54) ; T6.2 v2(59.74,39.99) ; v1(40.78,9.14) 40.69,9.23 40.69,9.25 40.41,9.53 Q3.2 ; T1.1 v5(77.57,42.15) ; C204.2 v5(1.32,46.21) ; v2(55.6,44.22) M1.GND5 v2(57.5,44.22) ; v5(94.99,7.91) TX2B.3 v5(97.92,7.91) ; Y2.2 v2(35.57,11.96) ; J3.6 v1(4.61,29.46) ; U16.5 v1(15.55,51.04) ; T6.5 v2(64.19,39.99) ; v1(29.52,13.7) 29.17,14.04 C58.2 28.34,14.04 v1(27.99,13.7) ; T8.1 v2(64.19,18.14) ; v5(92.84,15.3) TX2A.2 v5(89.91,15.3) ; v2(72.19,44.22) M1.GND2 74.35,44.22 ; Q4.2 v5(6.12,54.31) ; 39.76,53.98 v5(39.04,53.19) v5(39.68,53.83) 39.76,53.98
  L2_GND w0.14: 60.63,45.07 60.63,45.45 60.5,45.57
  L2_GND w0.203: v2(76.38,14.59) v2(76.89,14.59) v2(77.4,14.59) v2(77.9,14.59) v2(78.41,14.59) v2(79.05,14.59) v2(79.68,14.59) v2(80.44,14.59) v2(81.33,14.59) v2(81.97,14.59) v2(82.73,14.59) v2(83.36,14.59) 83.75,14.59 v2(83.87,14.46) 84,14.33
  L2_GND w0.254: v3(78.03,57.89) 77.66,57.52 77.66,57.5 ; 77.65,57 v3(78.03,56.62)
  BOTTOM w0.14: U3.J2 v4(50.59,40.28) ; U2.B9 v4(56.99,17.11) ; U2.A9 v4(56.99,16.31) ; U3.E1 v4(49.79,36.28) ; U3.E8 v4(56.19,36.28) ; U2.J2 v4(50.59,23.51) ; U2.G9 v4(56.99,21.11) ; U2.P1 v4(49.79,27.51) ; U3.B1 v4(49.79,33.88) ; U2.G1 v4(49.79,21.11) ; 56.59,28.71 v4(56.99,29.11) ; U2.M9 v4(56.99,25.91) ; U2.F9 v4(56.99,20.31) ; U3.T9 v4(56.99,45.88) ; U2.D8 v4(56.19,18.71) ; U3.E2 v4(50.59,36.28) ; U2.E2 v1(50.59,19.51) ; U3.T1 v1(49.79,45.88) ; U3.M9 v4(56.99,42.68) ; U3.D8 v4(56.19,35.48) ; U2.P9 v4(56.99,27.51) ; v4(56.99,33.88) U3.B9 ; U2.B1 v4(49.79,17.11) ; U3.D1 v4(49.79,35.48) ; U2.E8 v4(56.19,19.51) ; U3.G9 v4(56.99,37.88) ; U2.E1 v4(49.79,19.51) ; U3.G1 v4(49.79,37.88) ; U2.M1 v4(49.79,25.91) ; U2.D1 v4(49.79,18.71) ; U3.P1 v4(49.79,44.28) ; U3.G8 v4(56.19,37.88) ; U3.F9 v4(56.99,37.08) ; U2.J8 v4(56.19,23.51) ; U2.B3 v1(52.19,17.91) ; U3.P9 v4(56.99,44.28) ; U3.J8 v4(56.19,40.28) ; U2.T1 v4(49.79,29.11) ; U2.G8 v4(56.19,21.11) ; U3.M1 v4(49.79,42.68) ; U3.B3 v4(51.39,33.88)
  BOTTOM w0.254: v1(76.25,57.64) 76.26,57.64 U6.6 ; U14.8 46.48,59.42 46.63,59.27 v1(46.66,59.27) 46.69,59.27 46.84,59.42 U14.PAD 47.32,59.02 U14.4 ; R62.2 v4(74.47,41.51) ; R77.2 47.61,3.73 v1(47.42,3.92) ; C325.2 v6(69.2,26.49) ; v6(60.4,30.49) 60.49,30.4 C355.2 ; U6.PAD 79.55,57.64 U6.3 ; v6(70,27.29) 69.97,27.32 C1.2 ; C4.2 v6(68.4,28.89) 68.57,29.06 C322.2 ; C333.2 68.09,33.39 v6(68.4,33.69) ; R53.2 40.09,34.72 v1(40.22,34.59) ; v6(61.2,28.89) 61.2,28.9 C330.2 ; U3.A9 v4(56.99,33.88)
  BOTTOM w0.305: C84.2 v1(45.26,57.64) ; v1(41.22,31.59) 41.2,31.57 C249.2 ; v4(73.59,43.42) 73.59,43.67 73.86,43.94 U24.6 ; 75.63,45.44 v4(75.74,45.32) U24.PAD ; 75.63,45.44 U24.9 ; 75.63,45.44 v4(75.24,45.83) ; v6(60.4,32.89) 59.87,32.37 C348.2 ; R68.2 78.09,41.57 v4(78.41,41.89) ; C363.2 v4(60.03,21.28) ; v1(56.57,9.51) 56.73,9.67 JX2.65 ; C15.2 v5(37.9,47.73) ; C334.2 v1(69.78,23.98) ; C359.2 63.46,26.49 v6(63.6,26.49) 63.95,26.84 C319.2 ; v6(66,24.83) 65.98,24.83 65.81,25 C105.2 ; C76.2 37.33,22.7 v1(37.22,22.59) 36.95,22.32 C77.2 ; v1(33.22,37.59) 33.36,37.45 C179.2 ; C148.2 34.76,28.05 v1(35.22,27.59) ; v1(27.22,29.59) 27.1,29.7 C150.2 ; C357.2 v4(60.25,22.84) ; v1(33.22,40.59) 33.25,40.62 C154.2 ; C356.2 60.17,30.27 v6(60.4,30.49) ; R5.2 v1(71.87,57.7) ; C244.1 v1(6.47,27.98) ; C335.2 v1(64.19,36.56) ; R66.2 v4(73.97,49) ; v1(38.22,29.59) 38.41,29.78 C152.2 ; C354.2 v1(59.49,23.98) ; v6(65.2,27.29) 64.95,27.05 C360.2 ; v1(5.77,20.81) 5.96,20.62 C243.1 ; C93.2 v4(36.25,47.73) ; v1(59.23,8.11) 59.13,8 JX2.72 ; C90.2 v4(32.95,47.73) ; C104.1 60.44,25.74 v6(60.4,25.69) ; v6(67.6,34.49) 67.57,34.46 R125.2 ; C324.2 v4(72.32,38.72) ; C98.2 v5(39.42,47.73) ; R111.1 66.16,31.45 v6(66,31.29) ; v1(59.23,9.63) 59.23,9.78 59.13,9.89 JX2.71 ; C130.2 34.09,22.46 v1(33.22,21.59) ; R75.2 v4(94.67,31.99) ; C220.2 v4(15.42,38.84) ; C321.2 61.84,26.33 v6(62,26.49) ; C70.2 v4(29.9,47.73) ; C149.2 34.6,31.35 34.6,31.97 v1(35.22,32.59) 35.02,32.79 C198.2 ; C27.2 v5(40.95,47.73) ; v1(57.2,31.35) 56.06,31.35 55.17,30.46 55.17,29.83 54.41,29.06 v1(54.41,28.18) ; v6(69.2,32.89) 69.08,32.77 C326.2 ; C18.2 v4(31.42,47.73) ; R64.2 v4(77.27,49) ; JX3.61 v4(7.42,35.37) ; C19.1 v4(62.79,22.84) ; C17.2 v4(34.6,47.73) ; JX2.77 v4(61.53,11.91) ; C13.2 69.65,31.64 v6(69.2,32.09) 69.08,31.97 C329.2 ; C124.2 v4(70.83,47.26) ; C72.2 v5(42.47,47.73) ; v1(70.54,43.16) 70.03,42.65 C3.2 ; JX3.71 v4(6.78,39.37) ; C2.2 v4(75.87,31.6) ; JX2.91 v1(67.13,11.52) ; U21.4 v1(3.01,20.01)
  BOTTOM w0.381: C16.1 v1(69.65,40.37) ; JX2.92 v1(67.13,5.74) ; v1(83.36,17.25) 82.85,17.77 JX4.84 ; v1(83.11,12.68) 82.82,12.97 JX4.96 ; v1(83.11,16.11) 83.11,15.73 82.75,15.37 JX4.90 ; C14.1 v1(69.65,39.48)
  BOTTOM w0.457: v5(10.85,16.87) 11.18,17.21 11.18,17.37 11.58,17.77
  BOTTOM w0.508: JX4.95 v5(87.39,12.97) ; 11.58,17.77 JX3.18 ; JX1.72 v4(59.13,52.54) ; C125.2 47.42,3.16 v1(47.42,3.92) ; C144.2 17.36,28.94 17.07,28.65 v1(16.97,28.65) ; C12.2 v1(65.2,29.7) ; v5(41.58,57.51) 41.53,57.46 JX1.27 ; JX3.23 9.14,20.17 9.52,20.56 9.52,20.63 v5(9.7,20.81) ; C83.2 v5(30.6,60.24) ; v5(83.49,39.99) 82.88,39.37 JX4.30 ; v1(29.9,2.01) 29.39,2.52 C254.2 ; v5(17.71,14.59) 17.2,14.08 R50.2 ; C114.2 v1(28.12,47.23) ; C210.2 v4(22.15,15.98) v4(22.15,16.36) ; JX4.89 87.15,15.37 v5(87.56,14.97) ; v1(65.84,15.48) 65.55,15.77 C23.2 ; 83.36,2.39 84.12,1.63 v1(84.63,1.63) ; 83.36,2.39 C44.N 83.11,3.16 ; 83.36,2.39 v1(84.63,2.39) ; C134.2 v4(78.54,51.42) ; C160.2 v1(16.82,21.44) ; JX1.46 v4(48.73,52.47) ; v4(11.74,1.25) 11.74,2.27 12.37,2.9 ; JX3.84 v5(11.11,44.17) ; v5(87.81,40.24) 87.33,39.76 87.33,39.76 86.94,39.37 JX4.29 ; v5(42.34,52.94) 41.53,52.12 JX1.28 ; C166.2 22.02,46.21 v1(21.39,46.84) ; v5(4.5,15.6) 4.88,15.98 4.88,16.24 ; C174.2 v4(39.93,13.44) ; C74.2 v4(13.77,4.43) ; R116.2 v5(59.36,59.29) ; JX2.15 v1(36.73,12.15) ; JX4.50 v1(82.96,31.37) ; U8.2 v1(78.03,54.08) ; JX2.39 46.33,12.09 v4(46.53,12.3) ; JX2.46 48.73,7.76 v1(48.82,7.86) ; JX3.56 v1(10.94,32.97) ; v1(87.81,33.89) 87.81,34.99 87.43,35.37 JX4.39 ; JX4.24 v5(83.1,41.77) ; C308.2 12.24,6.08 11.86,6.46 11.86,6.84 ; C308.2 12.37,6.2 12.63,6.46 v1(12.63,7.73) ; C308.2 11.86,6.84 ; C308.2 11.86,6.2 ; C202.2 17.77,40.85 17.96,40.88 v1(18.72,40.88) ; v5(87.94,17.13) 87.29,17.77 JX4.83 ; C214.2 v4(14.53,8.11) ; C170.2 21.13,30.46 C175.2 ; JX3.29 v5(9.59,22.57) ; v1(48.69,9) 48.73,9.03 JX2.45 ; JX3.6 v1(11.26,12.97) ; C199.2 73.97,58.66 73.71,58.91 v5(73.08,58.91) ; JX2.27 v1(41.53,12.23) ; C185.2 v1(19.61,13.7) ; C136.2 v4(38.41,13.7) ; C184.2 20.33,55.23 v5(19.48,55.23) ; JX2.34 v1(43.93,5.06) ; JX3.89 9.3,46.57 v1(9.7,46.97) ; JX3.40 14.17,26.57 14.78,27.19 14.78,27.36 v1(14.91,27.49) ; v1(84.63,3.16) 83.11,3.16 ; 83.11,3.16 83.87,3.92 v1(84.63,3.92) ; JX2.16 v1(36.73,8.08) ; v1(23.17,13.7) 23.55,14.08 C153.2 ; v1(33.22,26.59) 33.41,26.78 C159.2 ; JX1.95 v5(68.73,53.92) ; JX3.17 v5(6.79,17.77) ; v5(94.99,38.39) 95.68,37.7 P1.B2 ; U6.PAD v5(79.3,59.54) ; C328.2 v1(73.2,30.97) ; C69.2 v1(57.33,3.41) ; JX2.40 v1(46.33,8.49) ; C129.2 v1(32.56,13.7) ; C131.2 v5(41.45,13.44) ; C28.2 v1(27.1,47.23) ; v1(14.53,11.67) 15.04,11.16 C219.2 ; JX1.16 36.73,52.21 v5(36.25,52.69) ; R21.2 v4(52.12,13.44) ; v5(9.45,44.18) 9.44,44.17 JX3.83 ; v5(72.44,3.54) 71.68,3.54 71.3,3.16 C173.2 71.3,2.65 71.64,2.31 72.36,2.31 v5(72.44,2.39) ; JX1.51 v5(51.13,53.98) ; JX1.77 v5(61.53,53.96) ; C146.2 v1(16.82,19.92) ; R20.2 v4(60.76,12.68) ; JX4.49 v1(87.32,31.37) ; v1(24.94,47.61) 24.94,47.35 C99.2 ; JX2.21 v1(39.13,9.59) ; C252.2 v4(35.23,1.63) ; v1(83.11,26.27) 82.81,26.57 JX4.62 ; JX3.96 v1(13.93,48.97) ; v1(83.21,36.41) 83.24,36.38 83.24,35.8 82.81,35.37 JX4.40 ; C71.2 46.03,46.97 v5(46.28,46.72) ; JX1.39 v5(46.33,54) ; JX3.12 11.46,15.37 v1(10.97,15.86) ; C80.2 51.23,58.53 51.61,58.53 v4(51.74,58.66) ; C101.2 50.85,49.37 50.89,49.41 50.89,49.55 51.13,49.79 JX1.52 v5(51.13,52.54) ; 11.86,6.84 11.86,6.97 v1(11.48,7.35) ; C361.2 v5(89.33,58.4) ; R59.2 v4(58.98,34.78) ; JX1.33 v5(43.93,54.02) ; v4(71.46,41.68) C158.2 v4(73.12,41.68) ; C221.2 18.85,43.8 v5(18.72,43.67) 18.34,44.05 C207.2 C213.2 ; JX4.5 v5(84.54,48.97) ; 83.75,44.69 83.23,44.17 JX4.18 ; 83.75,44.69 84.26,44.17 JX4.17 ; 83.75,44.69 v5(83.75,45.32) ; C110.2 44.12,14.08 44.31,13.63 v5(44.5,13.44) ; P1.A2 92.02,37.7 v5(92.84,36.89) ; R120.2 v4(62.66,58.53) ; v4(64.82,39.35) 65.24,39.77 C21.2 ; C82.2 v5(35.29,57.83) ; C127.2 v1(36.88,13.7) ; C43.1 46.53,61.2 v5(46.92,60.81) U14.PAD ; JX4.6 v5(82.95,48.97) ; C182.2 v5(21.26,47.99) 20.37,47.1 C223.2 ; C195.2 v4(55.04,13.44) ; C200.2 v5(83.24,56.12) ; JX3.35 v5(9.61,24.97) ; v1(16.18,18.65) 16.44,18.4 C132.2 ; C169.2 v1(21.13,13.7) ; C167.2 v4(16.82,26.02) ; C121.2 v4(31.04,13.7) ; JX1.65 v4(56.73,53.99) ; v1(19.23,49.26) R176.2 C215.2 ; C260.2 v1(75.96,56.46) ; JX3.65 v4(6.82,36.97) ; JX2.86 v1(64.73,7.89) ; JX1.66 v4(56.73,52.53) ; JX2.33 v1(43.93,9.69) ; C327.2 v5(72.57,35.16) ; C168.2 19.74,59.8 v1(19.61,59.93) ; C323.2 v1(72.44,26.4) ; JX2.51 v4(51.13,12.28) ; JX3.72 11.21,39.37 10.72,39.86 v5(10.72,41) ; C40.2 v1(63.55,47.61) ; C137.2 v4(34.09,13.7) ; JX4.71 84.27,22.57 v5(83.75,23.1) 83.22,22.57 JX4.72 ; C309.2 12.37,2.9 ; 12.37,2.9 12.88,2.39 v4(12.88,1.25) ; JX4.23 v5(87.33,41.77) ; JX3.95 v1(9.58,48.97) ; v5(36.25,53.83) 36.25,53.93 36.56,54.25 36.56,54.37 36.73,54.54 JX1.15 ; JX4.55 v1(87.27,28.97) ; JX1.34 v5(43.93,52.49) ; JX4.11 84.65,46.57 v5(83.75,47.48) 82.84,46.57 JX4.12 ; C111.2 v4(16.82,24.49) ; C31.2 v5(43.99,47.73) ; C358.2 v5(89.33,56.75) ; C177.2 v4(42.98,13.51) ; JX3.90 11.12,46.57 10.85,46.84 v1(10.85,47.35) ; v1(24.31,1.25) 24.06,1 C75.2 ; JX1.96 v5(68.73,52.53) ; C157.2 v1(26.21,13.7) ; C57.2 v5(6.02,9.25) ; C128.2 v1(29.52,13.7) ; C171.2 v1(16.82,34.4) ; v1(64.95,43.16) 65.24,42.87 C22.2 ; JX1.40 v5(46.33,52.48) ; C332.2 v4(75.49,22.21) ; C194.2 v4(48.57,13.44) ; v1(14.78,35.03) 14.45,35.37 JX3.62 ; C206.2 v4(14.53,6.59) ; JX1.85 v5(64.73,52.43) JX1.86 ; v1(10.97,19.43) 10.97,19.92 11.23,20.17 JX3.24 ; JX1.21 39.13,54.08 38.87,53.83 v5(38.41,53.83) ; JX3.50 v1(10.96,30.57) ; JX2.52 51.13,8.13 v1(51.61,8.62) ; C176.2 46.41,13.79 v1(46.13,13.51) ; JX1.71 v4(59.13,53.98) ; U2.T9 56.59,28.71 ; C186.2 v1(24.69,13.7) ; JX4.61 87,26.57 87.43,26.14 v5(87.43,25.51) 87.43,25.23 87.17,24.97 JX4.65 ; C222.2 v4(15.8,36.05) ; v5(39.68,52.43) 39.38,52.43 39.13,52.18 JX1.22 ; JX4.66 v1(82.83,24.97) ; JX2.28 v1(41.53,5.13) ; C336.2 v1(75.24,25.13) ; C181.2 v5(23.59,53.92) ; JX3.78 v5(10.98,41.77) ; JX1.45 v5(48.73,53.99) ; JX3.77 v5(9.95,41.77) ; C20.1 63.68,42.65 v4(64.06,43.03) ; C135.2 v1(16.82,22.97) ; JX4.56 v1(82.95,28.97) ; R135.2 v1(16.82,27.41) ; C133.2 v4(70.79,44.94) ; v1(61.65,43.16) 62.37,43.89 C24.2 ; JX3.55 v5(6.81,32.97) ; C147.2 v4(47.55,13.7) ; C126.2 v1(27.99,13.7) ; v4(61.14,46.49) R166.2 ; C331.2 v4(75.87,37.19) ; C212.2 v4(31.55,4.3) ; JX2.22 v1(39.13,8.02) ; R22.2 v4(63.43,21.06) ; JX3.49 v5(9.59,30.57) ; v1(46.15,2.27) 45.9,2.27 C258.2 46.41,1.89 v1(46.79,2.27) v1(46.15,2.27)
  vias: v1(11.74,6.84) v1(11.74,6.2) v1(14.91,19.92) v1(15.42,1.25) v1(15.42,0.74) v1(16.18,0.74) v1(16.82,0.74) v1(17.45,1.38) v1(17.45,0.74) v1(18.59,46.72) v1(18.85,47.1) v1(20.37,41.51) v1(21.01,40.62) v1(21.22,30.59) v1(21.64,45.19) v1(23.04,7.6) v1(23.04,7.22) v1(23.04,6.84) v1(23.04,6.46) v1(23.04,6.08) v1(23.04,5.7) v1(23.04,5.32) v1(23.55,7.6) v1(23.55,7.22) v1(23.55,6.84) v1(23.55,6.46) v1(23.55,6.08) v1(23.55,5.7) v1(23.55,5.32) v1(24.06,6.84) v1(24.06,6.46) v1(24.06,6.08) v1(24.06,5.7) v1(24.22,30.59) v1(26.85,5.95) v1(41.71,8.87) v1(44.22,30.59) v1(46.66,60.05) v1(46.66,58.78) v1(47.17,60.05) v1(47.17,59.24) v1(47.17,58.78) v1(47.22,30.59) v1(53.27,2.65) v1(57.84,52.43) v1(59.23,9.25) v1(59.23,8.87) v1(59.23,8.49) v1(59.74,9.51) v1(59.74,9.13) v1(59.74,8.74) v1(59.74,8.36) v1(59.74,7.98) v1(60.07,43.11) v1(60.25,9.51) v1(60.25,8.36) v1(60.25,7.98) v1(60.67,43.12) v1(60.76,9.51) v1(60.76,9.13) v1(60.76,8.74) v1(60.76,7.98) v1(61.14,9.63) v1(61.14,9.25) v1(61.14,8.87) v1(61.14,8.49) v1(67.74,13.19) v1(68,9.63) v1(68,8.87) v1(68.25,9.25) v1(68.51,9.63) v1(68.76,9.25) v1(69.01,9.63) v1(69.27,9.25) v1(69.52,9.63) v1(69.52,8.87) v1(75.53,11.92) v1(77.78,9.51) v1(77.78,9) v1(77.78,8.49) v1(77.78,7.98) v1(78.28,9.51) v1(78.28,9) v1(78.28,8.49) v1(78.28,7.98) v1(78.79,9.51) v1(78.79,9) v1(78.79,8.49) v1(78.79,7.98) v1(79.3,9.51) v1(79.3,9) v1(79.3,8.49) v1(80.19,11.92) v1(87.43,38.72) v1(87.91,28.99) v2(6.78,15.6) v2(6.78,15.09) v2(6.78,14.59) v2(6.78,14.08) v2(6.78,13.57) v2(7.29,15.6) v2(7.29,14.59) v2(7.29,14.08) v2(7.29,13.57) v2(7.8,15.6) v2(7.8,15.09) v2(7.8,14.08) v2(7.8,13.57) v2(8.05,44.69) v2(8.05,44.18) v2(8.05,43.67) v2(8.05,43.16) v2(8.05,42.53) v2(8.05,42.02) v2(8.05,41.51) v2(8.31,15.6) v2(8.31,15.09) v2(8.31,14.59) v2(8.31,13.57) v2(8.56,44.69) v2(8.56,43.67) v2(8.56,43.16) v2(8.56,42.53) v2(8.56,42.02) v2(8.56,41.51) v2(8.56,41) v2(8.82,15.6) v2(8.82,15.09) v2(8.82,14.59) v2(8.82,14.08) v2(8.82,13.57) v2(9.07,44.69) v2(9.07,43.67) v2(9.07,43.16) v2(9.07,42.53) v2(9.07,42.02) v2(9.07,41.51) v2(9.07,41) v2(10.34,44.05) v2(11.36,44.81) v2(11.36,43.54) v2(11.36,43.03) v2(11.36,42.53) v2(11.86,44.81) v2(11.86,44.05) v2(11.86,43.54) v2(11.86,43.03) v2(11.86,42.53) v2(11.86,42.02) v2(11.86,41.51) v2(21.9,54.34) v2(21.9,53.83) v2(21.9,53.32) v2(21.9,52.81) v2(21.9,52.31) v2(21.9,51.8) v2(22.15,51.42) v2(22.4,54.34) v2(22.4,53.83) v2(22.4,53.32) v2(22.4,52.81) v2(22.4,52.31) v2(22.4,51.8) v2(22.66,51.42) v2(22.91,54.34) v2(22.91,53.83) v2(22.91,53.32) v2(22.91,52.81) v2(22.91,52.31) v2(22.91,51.8) v2(23.17,51.42) v2(23.42,54.34) v2(23.42,53.32) v2(23.42,52.81) v2(23.67,51.42) v2(23.93,53.32) v2(23.93,52.81) v2(23.93,52.31) v2(23.93,51.8) v2(24.18,51.42) v2(24.44,53.83) v2(24.44,53.32) v2(24.44,52.81) v2(24.44,52.31) v2(24.44,51.8) v2(56.44,31.1) v2(56.95,31.1) v2(58.85,10.01) v2(58.85,9.38) v2(58.85,8.87) v2(58.85,8.36) v2(59.41,42.24) v2(59.49,10.01) v2(59.87,10.01) v2(60.04,42.27) v2(60.05,40.24) v2(60.38,10.01) v2(60.67,42.27) v2(60.66,19.86) v2(60.63,19.23) v2(60.63,18.6) v2(60.63,17.96) v2(60.69,40.24) v2(60.97,17.45) v2(60.89,10.01) v2(61,20.4) v2(61.15,42.65) v2(61.14,8.11) v2(61.32,40.24) v2(61.41,20.87) v2(61.59,17.38) v2(62.66,19.12) v2(62.66,18.49) v2(62.82,43.44) v2(62.92,19.5) v2(63.27,43.89) v2(63.27,21.1) v2(63.56,19.5) v2(63.61,41.98) v2(63.72,44.34) v2(64.07,42.42) v2(64.17,44.78) v2(64.19,19.5) v2(64.21,17.62) v2(64.21,16.98) v2(64.26,16.35) v2(64.52,42.87) v2(64.56,15.8) v2(64.62,45.23) v2(65.07,15.43) v2(65.09,45.66) v2(65.14,20.91) v2(65.42,43.77) v2(65.58,46.06) v2(65.59,20.47) v2(65.87,44.22) v2(65.8,19.88) v2(65.81,19.25) v2(65.81,18.61) v2(65.81,17.98) v2(65.81,17.34) v2(66.02,16.91) v2(66.11,46.42) v2(66.35,44.63) v2(66.33,15.31) v2(66.66,46.74) v2(66.65,16.91) v2(66.86,45) v2(66.96,15.31) v2(67.23,47.02) v2(67.41,45.32) v2(67.6,15.31) v2(67.82,47.25) v2(67.87,42.01) v2(67.87,41.38) v2(67.87,40.74) v2(67.92,16.91) v2(67.98,45.6) v2(68.06,42.6) v2(68,8.49) v2(68,8.11) v2(68.25,15.35) v2(68.42,47.45) v2(68.41,43.1) v2(68.38,8.49) v2(68.38,8.11) v2(68.54,39.86) v2(68.56,16.91) v2(68.58,45.82) v2(68.75,43.63) v2(68.76,8.49) v2(68.76,8.11) v2(68.89,15.35) v2(69.04,47.59) v2(69.17,39.86) v2(69.14,8.49) v2(69.14,8.11) v2(69.19,45.99) v2(69.19,44.09) v2(69.19,16.91) v2(69.5,15.31) v2(69.52,8.11) v2(69.67,47.7) v2(69.64,44.54) v2(69.65,9.25) v2(69.81,46.1) v2(69.95,42.56) v2(69.9,41.96) v2(69.9,41.32) v2(69.9,40.69) v2(69.9,9) v2(69.9,8.49) v2(69.9,8.11) v2(70.3,47.76) v2(70.45,46.16) v2(70.46,16.91) v2(70.56,45.41) v2(70.77,15.31) v2(70.83,43.47) v2(70.87,41.45) v2(70.82,40.82) v2(70.83,19.64) v2(70.79,19.01) v2(70.85,18.38) v2(70.93,47.77) v2(71.08,45.78) v2(71.08,46.17) v2(71.12,42.03) v2(71.1,16.91) v2(71.28,43.91) v2(71.3,20.03) v2(71.34,18.02) v2(71.41,15.31) v2(71.57,47.77) v2(71.55,42.5) v2(71.72,46.17) v2(71.77,44.32) v2(71.93,20.05) v2(71.97,18.02) v2(71.93,15.35) v2(72.12,42.78) v2(72.2,47.77) v2(72.19,17) v2(72.31,44.66) v2(72.42,40.63) v2(72.44,15.35) v2(72.53,41.22) v2(72.57,20.05) v2(72.61,18.02) v2(72.75,42.84) v2(72.84,47.77) v2(72.82,15.22) v2(72.88,44.93) v2(73,16.86) v2(73.2,20.03) v2(73.24,18.04) v2(73.27,15.09) v2(73.33,43.08) v2(73.47,47.77) v2(73.48,45.13) v2(73.61,16.69) v2(73.76,14.68) v2(73.81,43.5) v2(73.78,19.81) v2(74.09,47.73) v2(74.11,45.24) v2(74.26,43.95) v2(74.22,19.67) v2(74.27,17.72) v2(74.21,14.23) v2(74.44,16.5) v2(74.47,16.11) v2(74.66,13.79) v2(74.73,47.73) v2(74.74,45.28) v2(74.71,44.4) v2(74.73,19.41) v2(75.15,44.85) v2(75.24,18.9) v2(75.18,13.42) v2(75.36,47.9) v2(75.36,20.13) v2(75.4,20.76) v2(75.6,45.29) v2(75.66,21.32) v2(75.69,43.12) v2(75.74,18.4) v2(75.76,13.17) v2(76.14,43.57) v2(76.13,17.76) v2(76.25,17.13) v2(76.25,16.62) v2(76.4,48.62) v2(76.38,13.06) v2(76.51,16.24) v2(76.59,44.02) v2(76.84,49.07) v2(76.89,46.97) v2(77.01,13.06) v2(77.11,44.38) v2(77.1,16.07) v2(77.29,49.52) v2(77.37,21.86) v2(77.37,18.74) v2(77.4,47.35) v2(77.41,40.14) v2(77.4,39.5) v2(77.41,26.55) v2(77.4,25.91) v2(77.4,20.01) v2(77.4,19.37) v2(77.5,38.88) v2(77.65,13.06) v2(77.74,49.97) v2(77.77,20.26) v2(77.82,40.59) v2(77.79,37.31) v2(77.78,36.68) v2(77.78,36.04) v2(77.79,35.41) v2(77.82,27) v2(77.78,25.38) v2(78,21.86) v2(78.09,48.05) v2(78.18,37.78) v2(78.19,34.95) v2(78.31,25) v2(78.28,13.06) v2(78.38,44.39) v2(78.45,40.62) v2(78.45,27.03) v2(78.41,20.26) v2(78.54,48.5) v2(78.52,38.59) v2(78.78,51.51) v2(78.79,47.35) v2(78.81,37.83) v2(78.78,34.74) v2(78.92,13.06) v2(79.05,49) v2(79.01,44.44) v2(79.02,20.21) v2(79.17,42.02) v2(79.09,40.62) v2(79.16,38.59) v2(79.09,27.03) v2(79.25,51.93) v2(79.43,37.77) v2(79.42,34.74) v2(79.57,44.72) v2(79.51,19.81) v2(79.55,13.06) v2(79.67,27.26) v2(79.72,40.62) v2(79.82,52.22) v2(79.79,38.6) v2(79.8,37.29) v2(79.81,36.65) v2(80.16,25.22) v2(80.25,47.39) v2(80.19,13.06) v2(80.35,38.87) v2(80.44,52.34) v2(80.59,50.74) v2(80.72,41.2) v2(80.77,36.34) v2(80.69,34.74) v2(80.77,19.77) v2(80.82,44.77) v2(80.82,13.02) v2(80.88,47.39) v2(80.9,39.17) v2(80.93,27.32) v2(80.91,16.07) v2(81.07,52.34) v2(81.05,25.72) v2(81,21.37) v2(81.22,50.74) v2(81.29,41.47) v2(81.35,39.62) v2(81.32,34.74) v2(81.43,44.6) v2(81.4,36.34) v2(81.41,19.77) v2(81.46,13.02) v2(81.52,47.39) v2(81.49,27.54) v2(81.54,16.07) v2(81.64,21.37) v2(81.71,52.34) v2(81.68,25.8) v2(81.86,50.74) v2(81.86,39.95) v2(81.88,44.15) v2(81.92,41.55) v2(81.88,34.5) v2(82.03,36.27) v2(82.07,27.8) v2(82.04,19.78) v2(82.15,47.39) v2(82.09,13.02) v2(82.25,26.08) v2(82.2,21.59) v2(82.18,16.07) v2(82.34,52.34) v2(82.38,43.77) v2(82.49,50.74) v2(82.56,41.55) v2(82.5,39.95) v2(82.5,34.36) v2(82.58,35.96) v2(82.65,22.04) v2(82.65,19.95) v2(82.7,27.83) v2(82.73,16.11) v2(82.73,13.06) v2(82.79,47.39) v2(82.86,45.79) v2(82.97,43.55) v2(83.13,50.74) v2(83.13,34.36) v2(83.09,22.49) v2(83.18,45.15) v2(83.22,35.96) v2(83.18,20.31) v2(83.34,27.83) v2(83.5,45.79) v2(83.61,43.5) v2(83.6,42.18) v2(83.63,20.75) v2(83.63,19.06) v2(83.62,16.11) v2(83.76,50.74) v2(83.77,34.36) v2(83.75,27.79) v2(83.73,17.47) v2(83.72,12.59) v2(83.85,35.96) v2(84.07,21.2) v2(84.1,26.23) v2(84.12,23.22) v2(84.26,19.07) v2(84.25,14.33) v2(84.37,17.47) v2(84.4,50.74) v2(84.69,47.39) v2(84.73,26.23) v2(84.86,42.31) v2(84.8,40.71) v2(84.88,43.5) v2(84.9,19.07) v2(85.03,50.74) v2(85.04,34.36) v2(85,17.47) v2(85.08,45.1) v2(85.12,35.96) v2(85.13,21.87) v2(85.08,11.26) v2(85.24,27.83) v2(85.2,13.37) v2(85.33,47.39) v2(85.37,26.23) v2(85.35,23.51) v2(85.35,16.03) v2(85.4,45.79) v2(85.44,40.71) v2(85.52,52.34) v2(85.51,43.5) v2(85.49,42.31) v2(85.53,19.07) v2(85.52,14.21) v2(85.67,50.74) v2(85.67,34.36) v2(85.64,17.47) v2(85.65,12.92) v2(85.58,10.86) v2(85.71,45.1) v2(85.76,35.96) v2(85.76,21.91) v2(85.85,13.92) v2(85.96,47.39) v2(85.88,27.83) v2(85.96,15.84) v2(86.04,45.79) v2(85.98,40.46) v2(86,26.23) v2(86.15,52.34) v2(86.15,43.5) v2(86.12,42.26) v2(86.13,23.51) v2(86.17,19.07) v2(86.12,12.49) v2(86.09,10.49) v2(86.27,17.47) v2(86.3,50.74) v2(86.35,45.1) v2(86.31,34.36) v2(86.37,13.55) v2(86.39,35.96) v2(86.39,21.91) v2(86.56,40.22) v2(86.51,27.83) v2(86.49,15.5) v2(86.6,47.39) v2(86.67,45.79) v2(86.64,26.23) v2(86.61,12.08) v2(86.62,10.14) v2(86.68,41.98) v2(86.76,23.51) v2(86.79,52.34) v2(86.78,43.5) v2(86.8,19.07) v2(86.94,34.36) v2(86.91,17.47) v2(86.96,15.07) v2(86.94,13.28) v2(86.98,45.1) v2(87.03,35.96) v2(87.03,21.91) v2(87.15,27.83) v2(87.13,11.72) v2(87.19,40.2) v2(87.27,26.23) v2(87.18,9.83) v2(87.31,45.82) v2(87.42,52.43) v2(87.42,43.5) v2(87.4,23.51) v2(87.44,19.07) v2(87.54,17.47) v2(87.62,45.1) v2(87.66,35.96) v2(87.58,34.36) v2(87.66,21.91) v2(87.67,11.39) v2(87.75,9.55) v2(87.78,27.83) v2(87.92,45.96) v2(87.88,41.8) v2(87.91,26.23) v2(88.01,52.65) v2(88.05,43.5) v2(88.03,23.51) v2(88.07,19.07) v2(88.13,14.63) v2(88.18,50.99) v2(88.25,45.1) v2(88.25,36.14) v2(88.21,34.37) v2(88.18,17.47) v2(88.18,13.03) v2(88.23,11.09) v2(88.3,48.08) v2(88.3,21.91) v2(88.33,9.31) v2(88.43,40.01) v2(88.42,27.83) v2(88.53,53.01) v2(88.51,46.22) v2(88.51,41.73) v2(88.54,26.23) v2(88.67,23.51) v2(88.69,53.58) v2(88.76,51.24) v2(88.75,48.52) v2(88.69,43.5) v2(88.71,19.07) v2(88.77,14.63) v2(88.84,45.21) v2(88.83,36.3) v2(88.79,34.58) v2(88.87,21.78) v2(88.81,17.47) v2(88.79,12.99) v2(88.81,10.84) v2(88.89,54.16) v2(88.89,39.57) v2(88.93,9.1) v2(89.03,46.57) v2(89.05,27.83) v2(89.1,41.49) v2(89.26,48.9) v2(89.22,43.18) v2(89.18,26.23) v2(89.18,23.83) v2(89.3,51.58) v2(89.33,19.07) v2(89.28,14.95) v2(89.35,12.69) v2(89.42,45.43) v2(89.43,39.25) v2(89.41,36.54) v2(89.45,21.58) v2(89.45,17.47) v2(89.41,10.62) v2(89.5,54.32) v2(89.49,47.01) v2(89.54,8.92) v2(89.6,41.1) v2(89.69,27.83) v2(89.83,49.19) v2(89.85,43.17) v2(89.81,26.23) v2(89.96,47.44) v2(89.97,19.07) v2(90.05,45.43) v2(90.04,39.08) v2(90.04,36.54) v2(90.02,10.45) v2(90.09,40.71) v2(90.08,21.58) v2(90.08,17.47) v2(90.16,8.78) v2(90.32,27.83) v2(90.39,52.06) v2(90.42,49.4) v2(90.45,26.23) v2(90.45,23.84) v2(90.51,47.75) v2(90.49,43.19) v2(90.5,34.3) v2(90.55,14.93) v2(90.67,39.06) v2(90.6,19.07) v2(90.62,12.75) v2(90.64,10.32) v2(90.72,40.66) v2(90.72,17.47) v2(90.79,8.68) v2(90.96,27.83) v2(91.05,49.52) v2(91.12,47.92) v2(91.08,26.23) v2(91.25,19.07) v2(91.27,10.23) v2(91.35,40.66) v2(91.31,39.06) v2(91.35,17.47) v2(91.42,8.61) v2(91.59,27.83) v2(91.75,47.95) v2(91.72,26.23) v2(91.94,39.06) v2(91.88,19.07) v2(91.91,10.19) v2(91.99,40.66) v2(91.99,17.47) v2(92.05,8.58) v2(92.17,49.55) v2(92.23,27.83) v2(92.35,26.23) v2(92.39,47.95) v2(92.52,19.07) v2(92.54,10.18) v2(92.62,40.66) v2(92.58,39.06) v2(92.62,17.47) v2(92.69,8.58) v2(92.8,49.55) v2(92.86,27.83) v2(93.02,47.95) v2(92.99,26.23) v2(93.15,19.07) v2(93.18,10.18) v2(93.27,54.46) v2(93.26,40.66) v2(93.21,39.06) v2(93.26,17.47) v2(93.32,8.58) v2(93.44,49.55) v2(93.5,27.83) v2(93.66,47.95) v2(93.62,26.23) v2(93.87,40.7) v2(93.85,39.06) v2(93.79,19.07) v2(93.87,17.43) v2(93.81,10.18) v2(93.91,54.46) v2(93.97,28.12) v2(93.91,8.49) v2(93.99,49.72) v2(94.19,47.66) v2(94.21,26.06) v2(94.36,38.73) v2(94.3,19.39) v2(94.32,10.5) v2(94.43,40.99) v2(94.47,8.25) v2(94.54,54.46) v2(94.57,28.29) v2(94.49,17.14) v2(94.59,49.88) v2(94.84,26.03) v2(94.94,19.4) v2(95.13,17.14) v2(95.18,54.46) v2(95.21,28.29) v2(95.45,47.62) v2(95.47,26.03) v2(95.57,19.39) v2(95.63,38.76) v2(95.59,10.49) v2(95.7,40.94) v2(95.81,54.46) v2(96.45,54.46) v2(97.08,54.46) v2(97.72,54.46) v2(98.35,54.46) v2(98.99,54.46) v2(98.99,53.83) v2(98.99,53.19) v2(98.99,52.56) v2(98.99,51.92) v2(98.99,51.29) v2(98.99,50.65) v2(98.99,50.02) v2(98.99,49.38) v2(98.99,48.75) v2(98.99,48.11) v2(98.99,47.48) v2(98.99,46.84) v2(98.99,46.21) v2(98.99,45.57) v2(98.99,44.94) v2(98.99,44.3) v2(98.99,43.67) v2(98.99,43.03) v2(98.99,42.4) v2(98.99,41.76) v2(98.99,41) v2(98.99,40.37) v2(98.99,39.73) v2(98.99,39.1) v2(98.99,38.46) v2(98.99,37.83) v2(98.99,37.19) v2(98.99,36.56) v2(98.99,35.92) v2(98.99,35.29) v2(98.99,34.78) v2(98.99,34.14) v2(98.99,33.51) v2(98.99,32.87) v2(98.99,32.24) v2(98.99,31.6) v2(98.99,30.97) v2(98.99,30.33) v2(98.99,29.7) v2(98.99,29.06) v2(98.99,28.43) v2(98.99,27.79) v2(98.99,27.16) v2(98.99,26.52) v2(98.99,26.02) v2(98.99,25.38) v2(98.99,24.75) v2(98.99,24.11) v2(98.99,23.48) v2(98.99,22.84) v2(98.99,22.21) v2(98.99,21.57) v2(98.99,20.94) v2(98.99,20.3) v2(98.99,19.54) v2(98.99,18.9) v2(98.99,18.27) v2(98.99,17.63) v2(98.99,17) v2(98.99,16.36) v2(98.99,15.73) v2(98.99,15.09) v2(98.99,14.46) v2(98.99,13.82) v2(98.99,13.19) v2(98.99,12.55) v2(98.99,11.92) v2(98.99,11.28) v2(98.99,10.65) v2(98.99,10.01) v2(98.99,9.38) v2(98.99,8.74) v2(98.99,8.11) v2(98.99,7.47) v3(41.71,4.43) v3(59.36,19.41) v3(61.52,17.89) v3(66.98,52.81) v4(20.37,9.13) v4(20.37,8.62) v4(20.37,8.11) v4(20.37,7.6) v4(20.88,7.6) v4(20.88,7.09) v4(20.88,6.59) v4(20.88,6.08) v4(20.88,5.57) v4(21.39,9.13) v4(21.39,8.62) v4(21.39,8.11) v4(21.39,7.6) v4(21.39,7.09) v4(21.39,6.59) v4(21.77,15.98) v4(21.77,15.48) v4(21.9,8.62) v4(21.9,8.11) v4(22.15,15.48) v4(22.4,8.11) v4(22.4,7.6) v4(22.53,15.98) v4(22.53,15.48) v4(22.66,8.49) v4(22.91,8.11) v4(23.42,8.11) v4(75.24,45.32) v4(75.24,44.81) v4(75.24,44.3) v4(75.24,43.8) v4(75.74,45.83) v4(75.74,44.81) v4(75.74,44.3) v4(75.74,43.8) v4(76.25,45.83) v4(76.25,45.32) v4(76.25,44.81) v4(76.25,44.3) v4(76.25,43.8) v4(76.76,45.83) v4(76.76,45.32) v4(76.76,44.81) v4(76.76,44.3) v4(76.76,43.8) v4(77.27,45.83) v4(77.27,45.32) v4(77.27,44.81) v4(77.27,44.3) v4(77.27,43.8) v4(78.54,58.78) v4(78.54,58.27) v4(78.54,57.77) v4(78.54,57.26) v4(78.54,56.75) v4(79.05,58.78) v4(79.05,58.27) v4(79.05,56.75) v4(79.55,58.78) v4(79.55,58.27) v4(79.55,57.89) v4(79.55,57.26) v4(79.55,56.75) v4(80.06,58.78) v4(80.06,58.27) v4(80.06,57.77) v4(80.06,57.26) v4(80.06,56.75) v5(9.83,42.78) v5(10.34,44.81) v5(10.59,43.16) v5(10.59,42.4) v5(21.39,53.96) v5(21.39,53.19) v5(21.39,52.56) v5(21.39,51.92) v5(23.42,52.05) v5(24.18,54.34) v5(38.41,53.19) v5(38.41,52.43) v5(39.04,53.83) v5(39.04,52.43) v5(39.68,53.19) v5(61.52,17) v5(67.11,17.13) v5(71.68,17) v5(77.78,17.13) v5(79.3,25)
